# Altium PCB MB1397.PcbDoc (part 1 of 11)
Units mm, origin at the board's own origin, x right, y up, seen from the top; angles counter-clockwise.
Board outline 118.24 x 172.86 mm, 6 copper layers (Top Layer, L2_GND, L3_VCC, L4_SIG, L5_GND, Bottom Layer), stack 1.631 mm thick; 819 components, 632 nets, 2875 pads, 1523 vias.
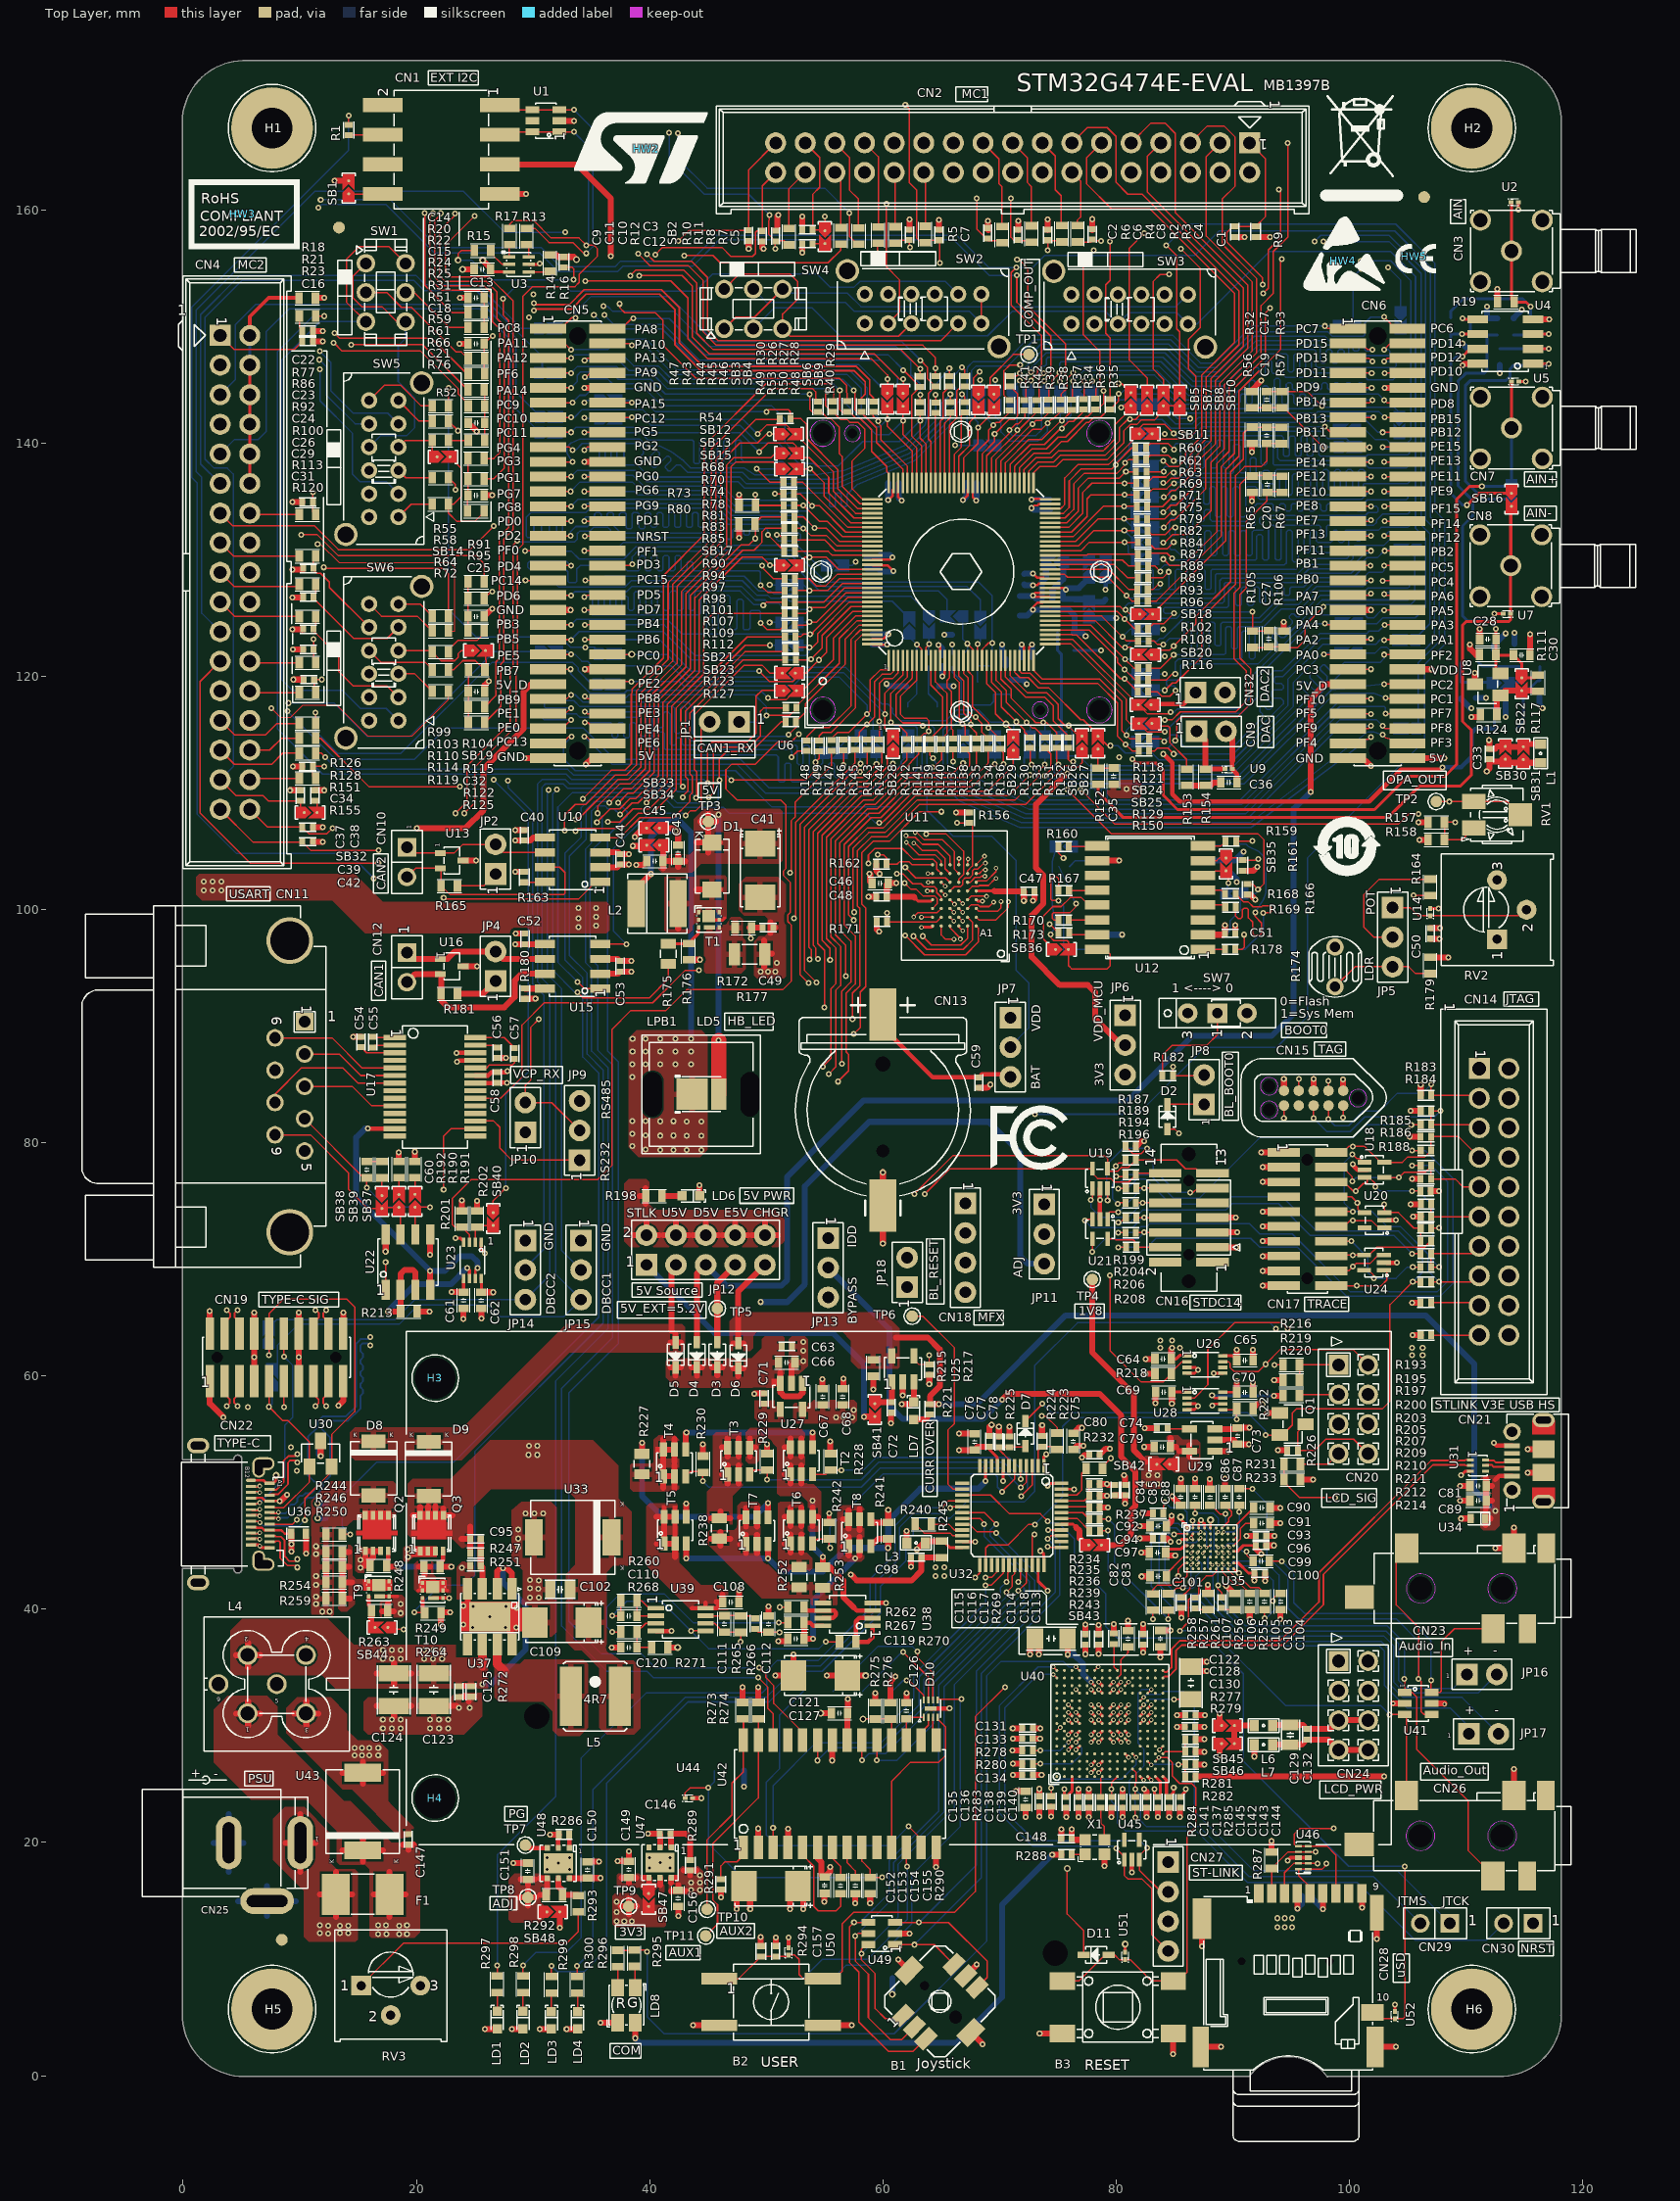
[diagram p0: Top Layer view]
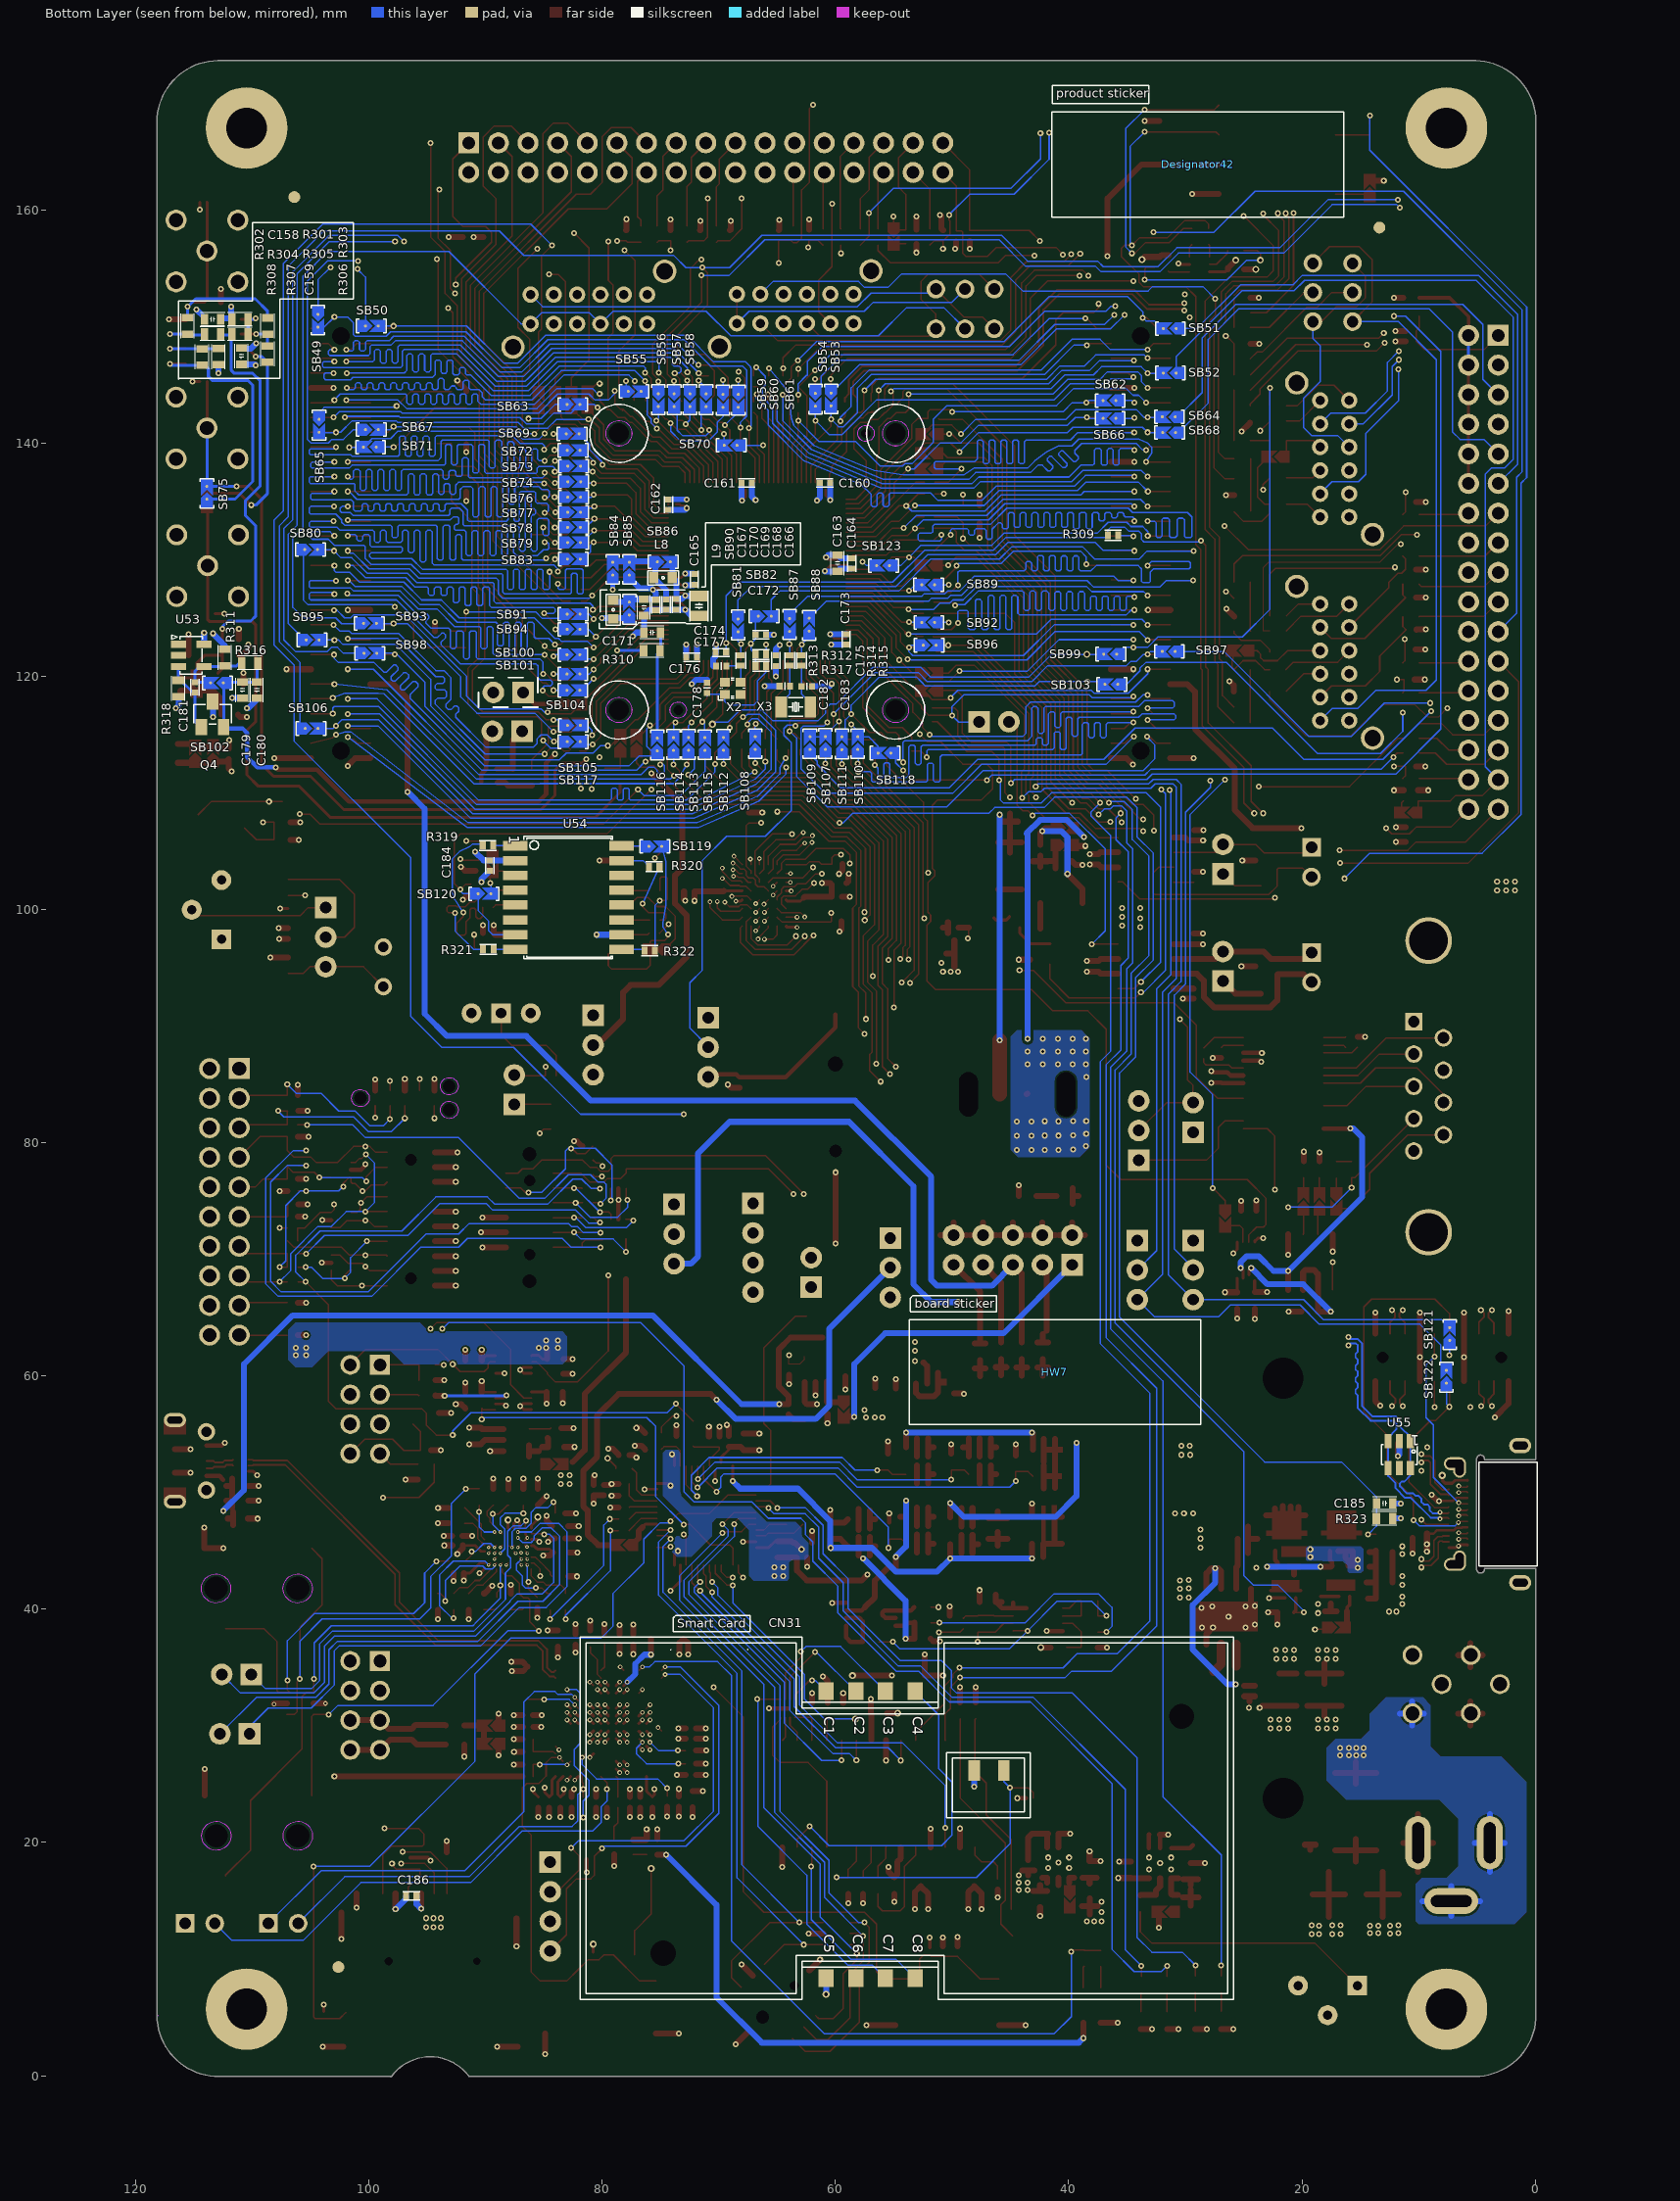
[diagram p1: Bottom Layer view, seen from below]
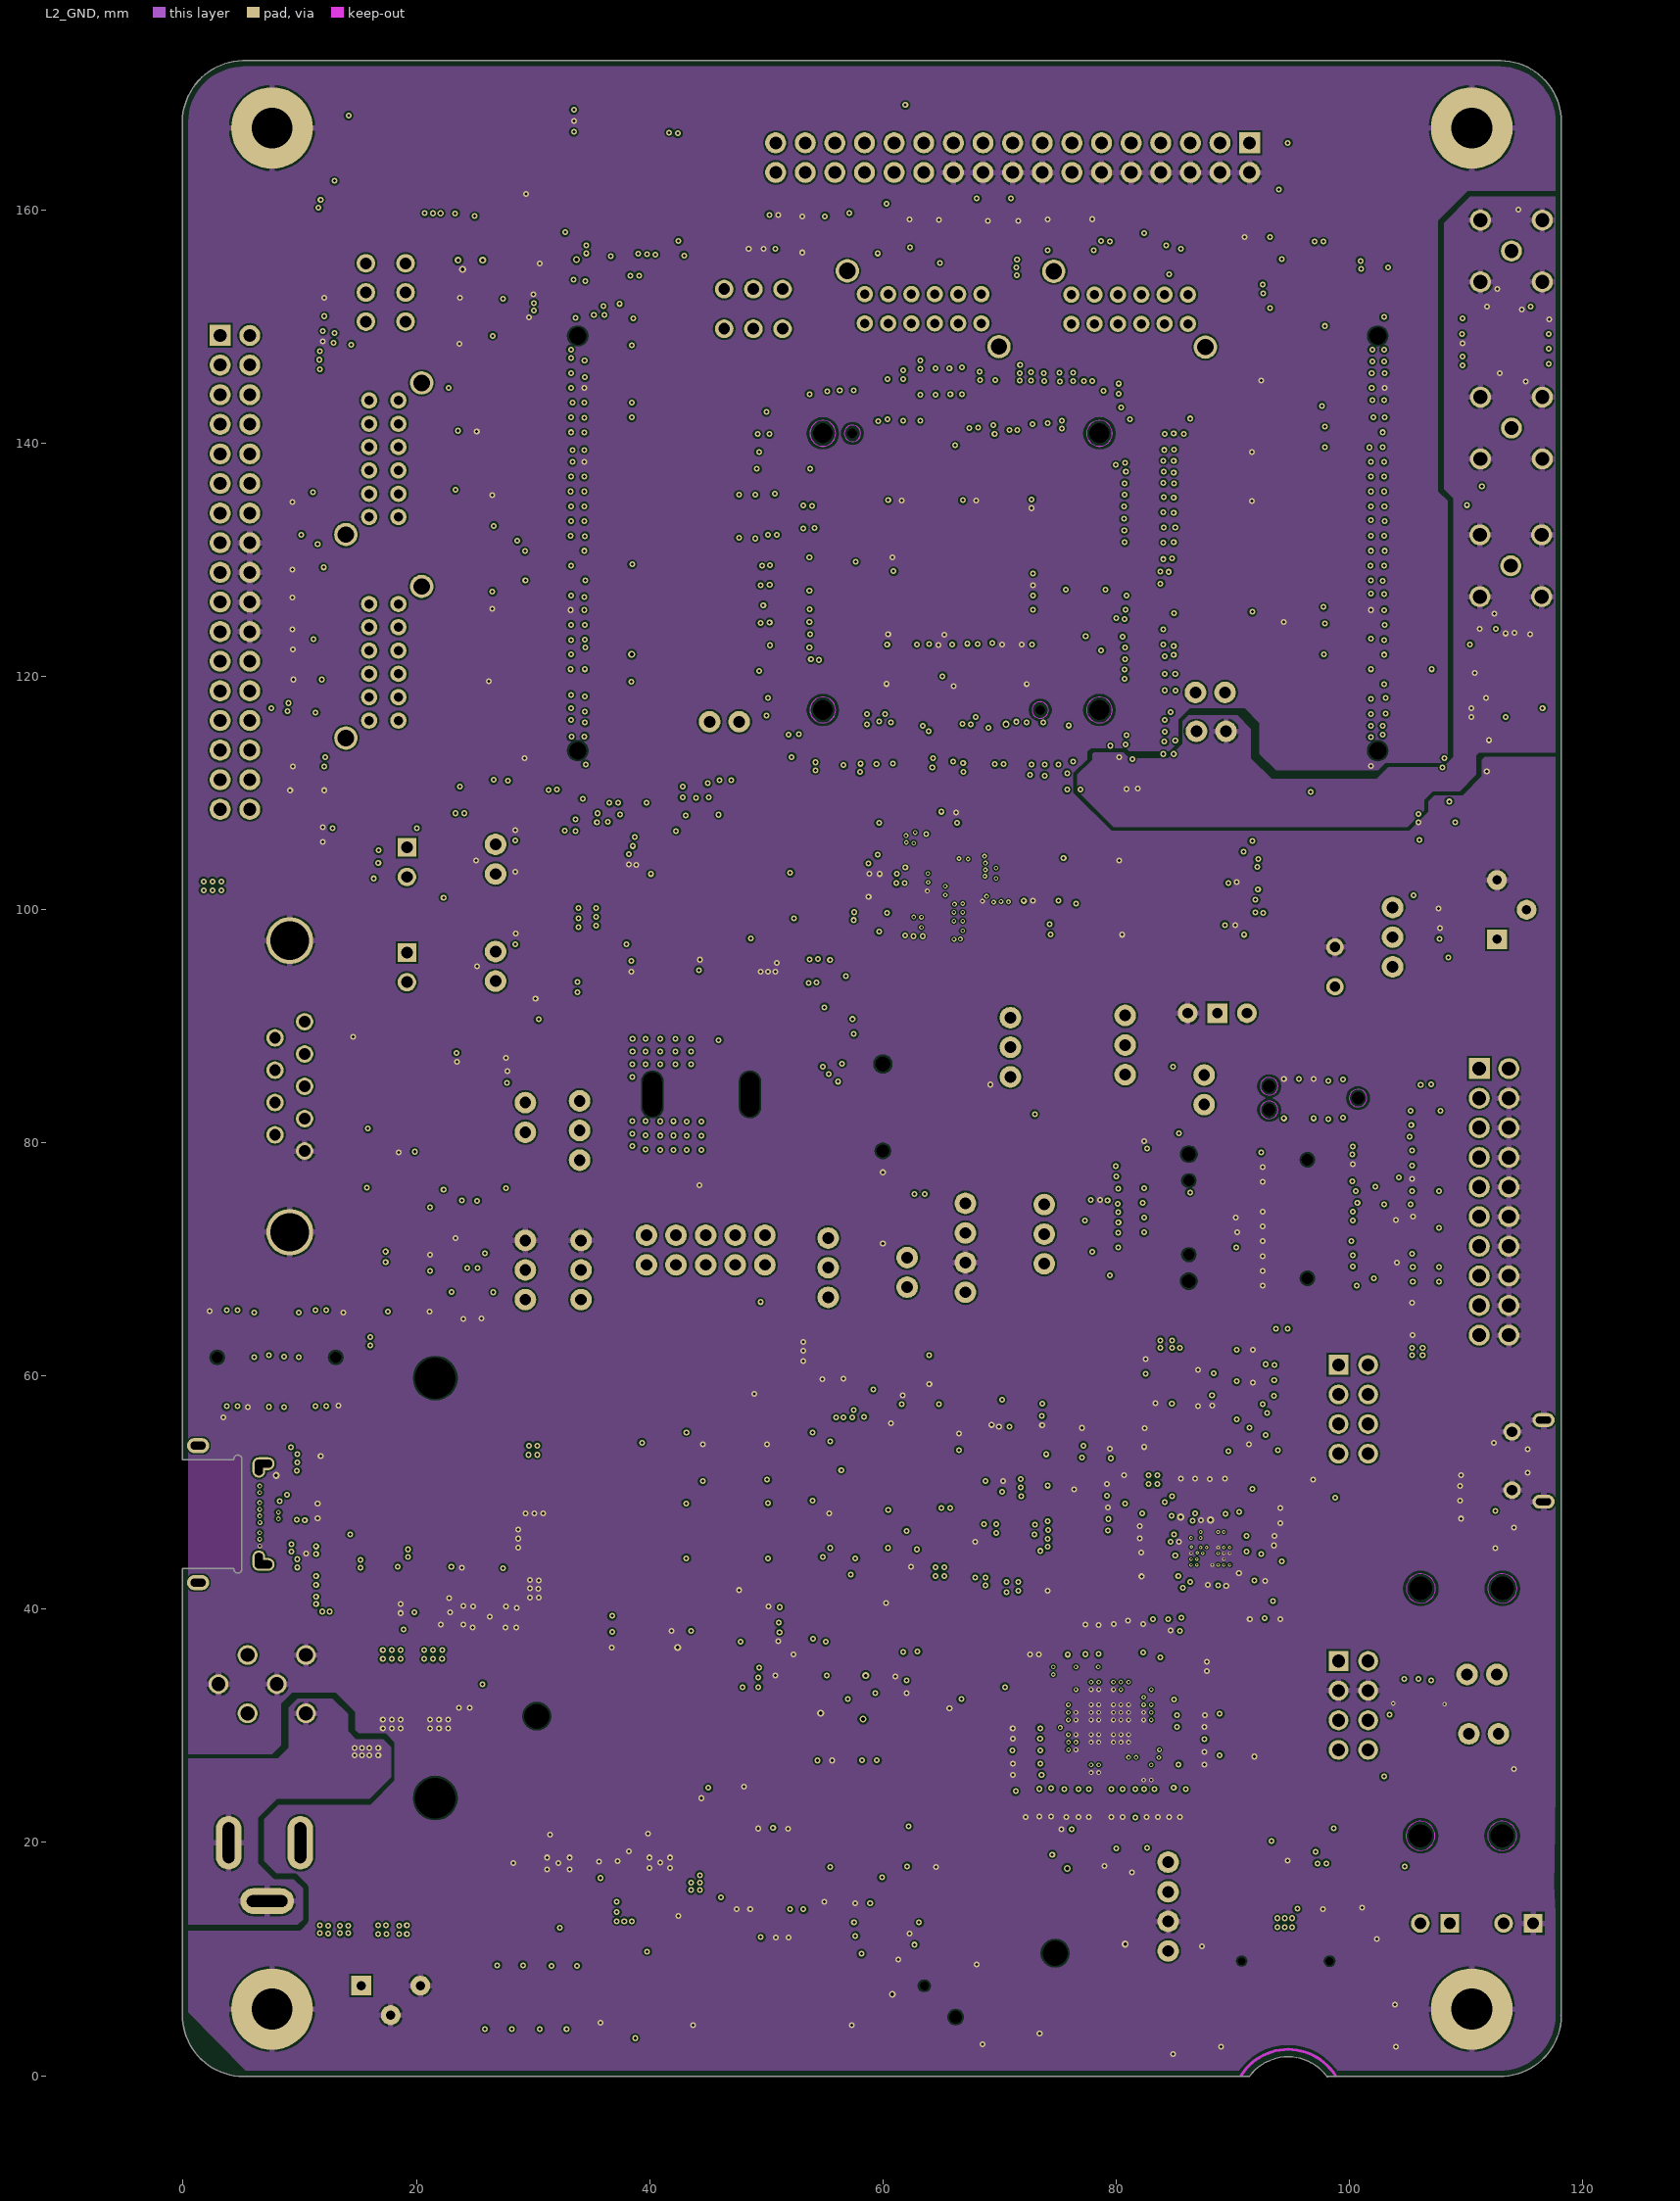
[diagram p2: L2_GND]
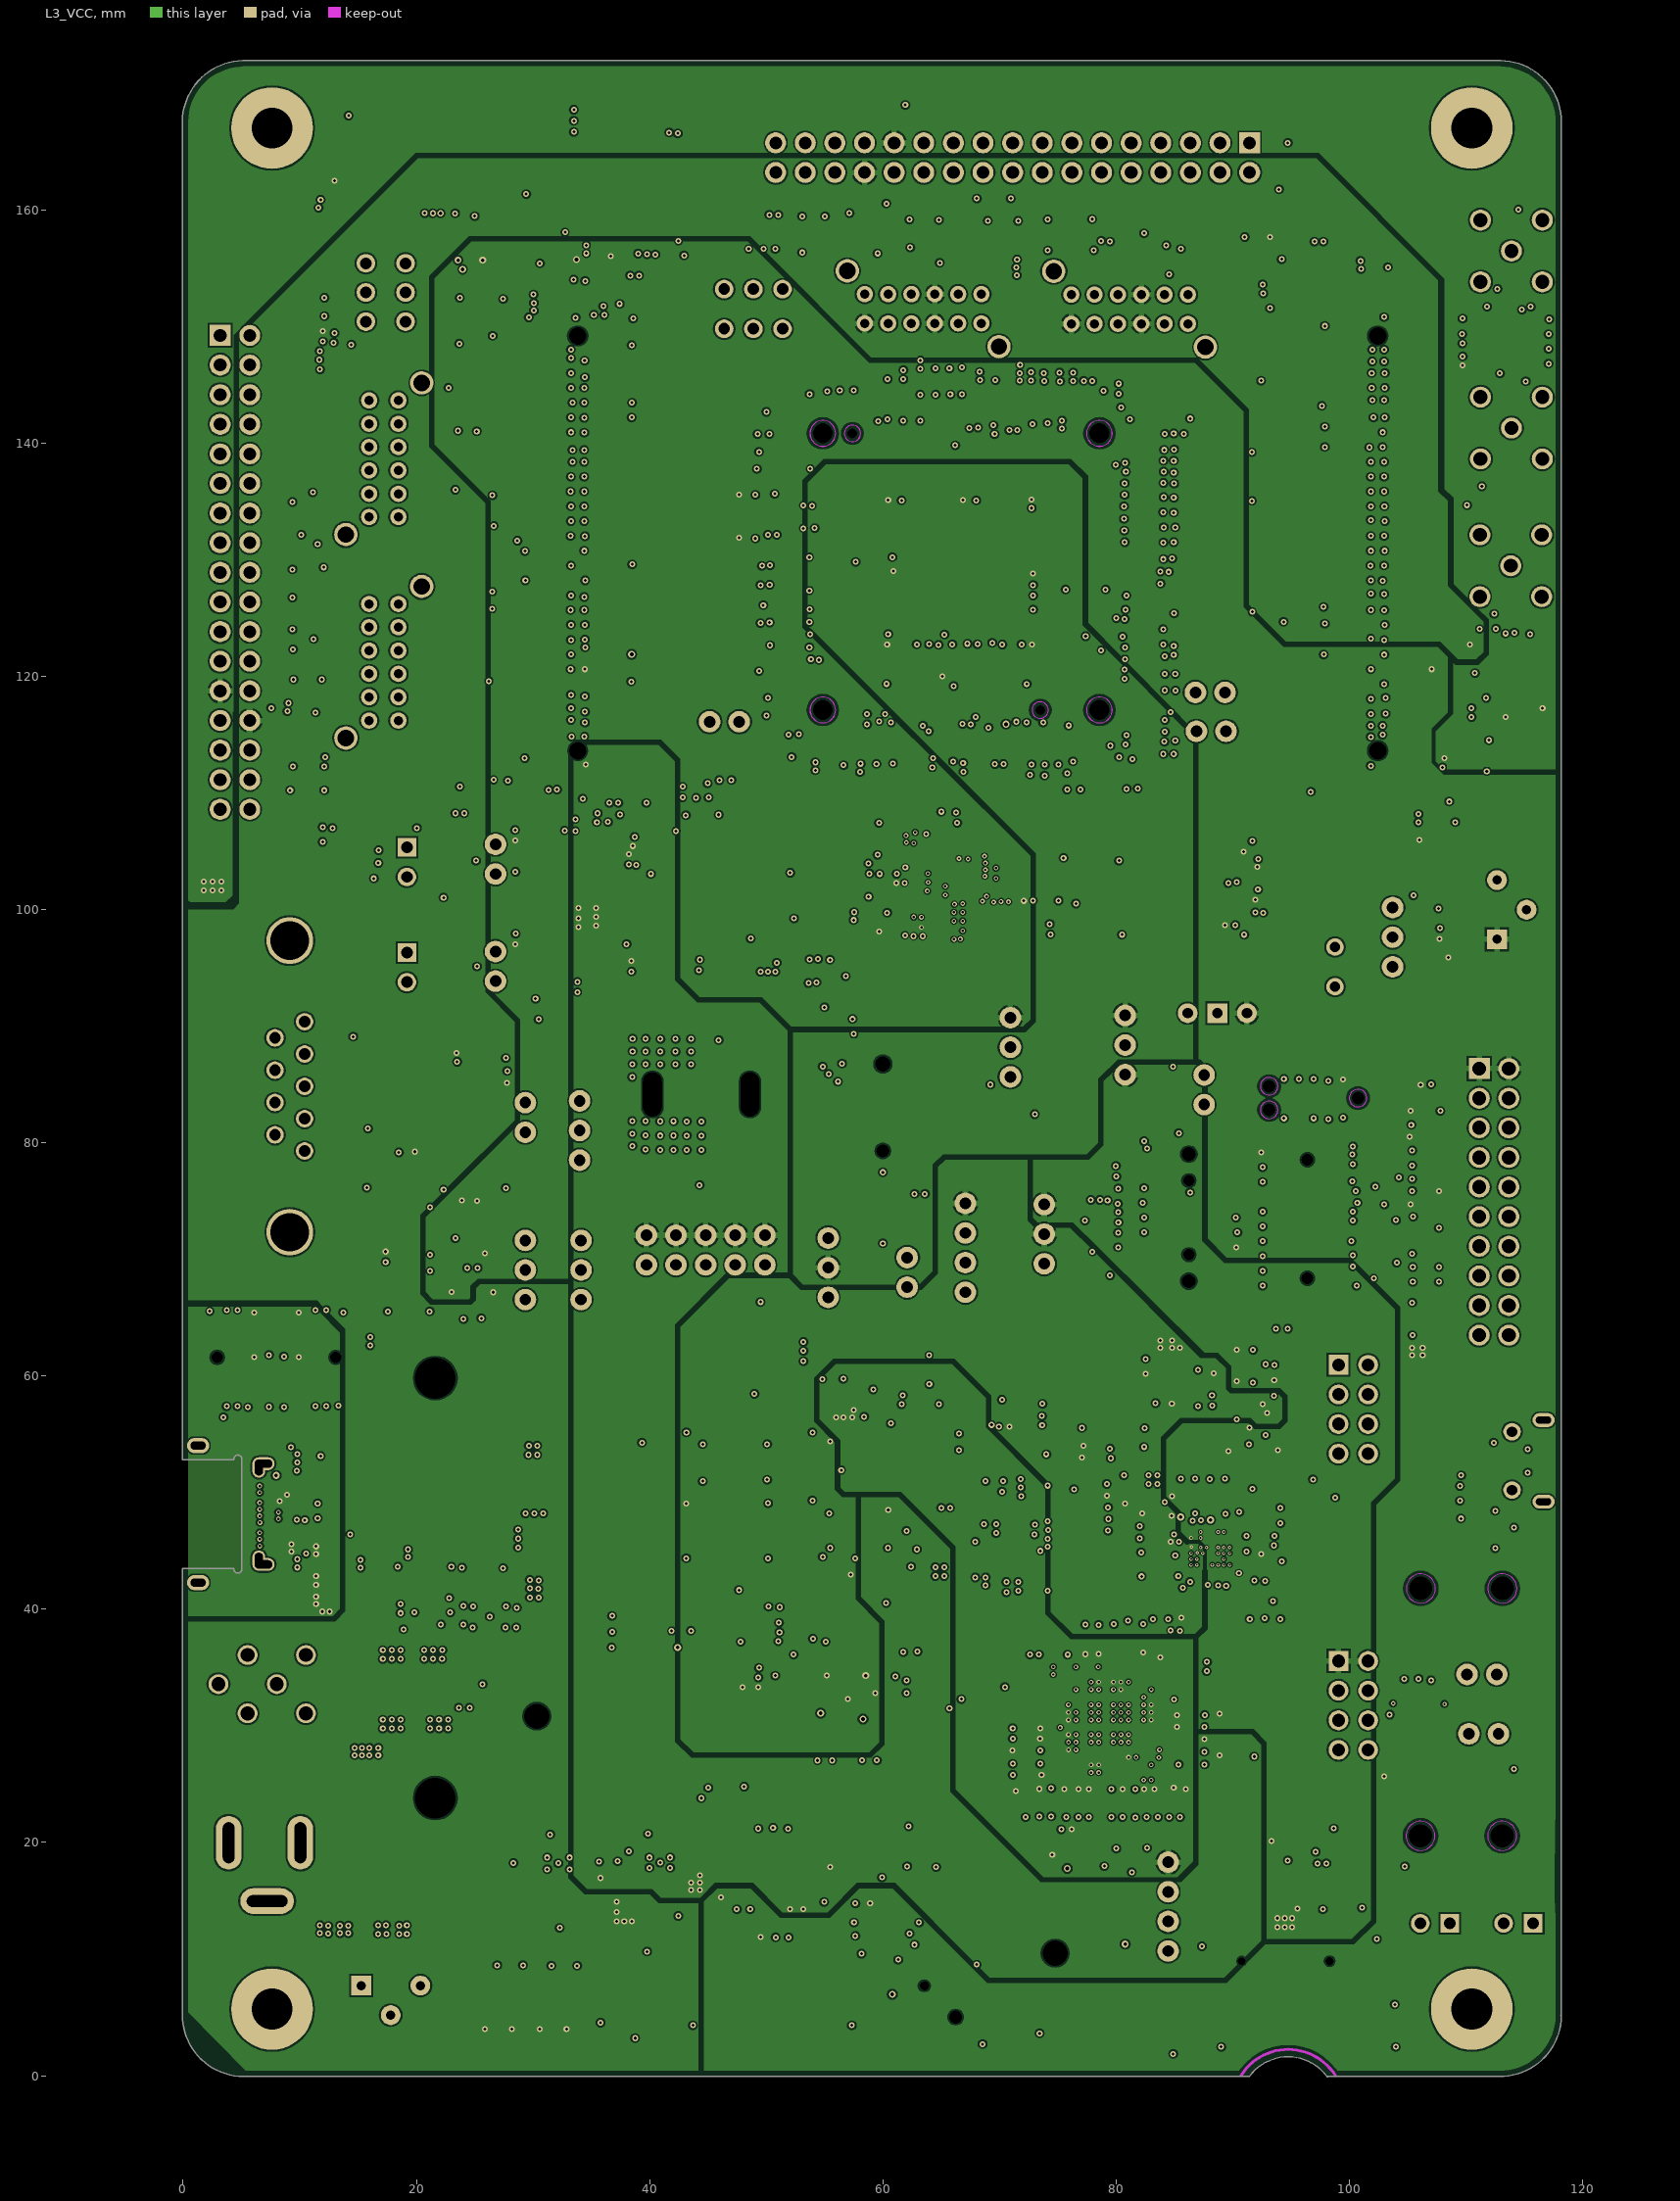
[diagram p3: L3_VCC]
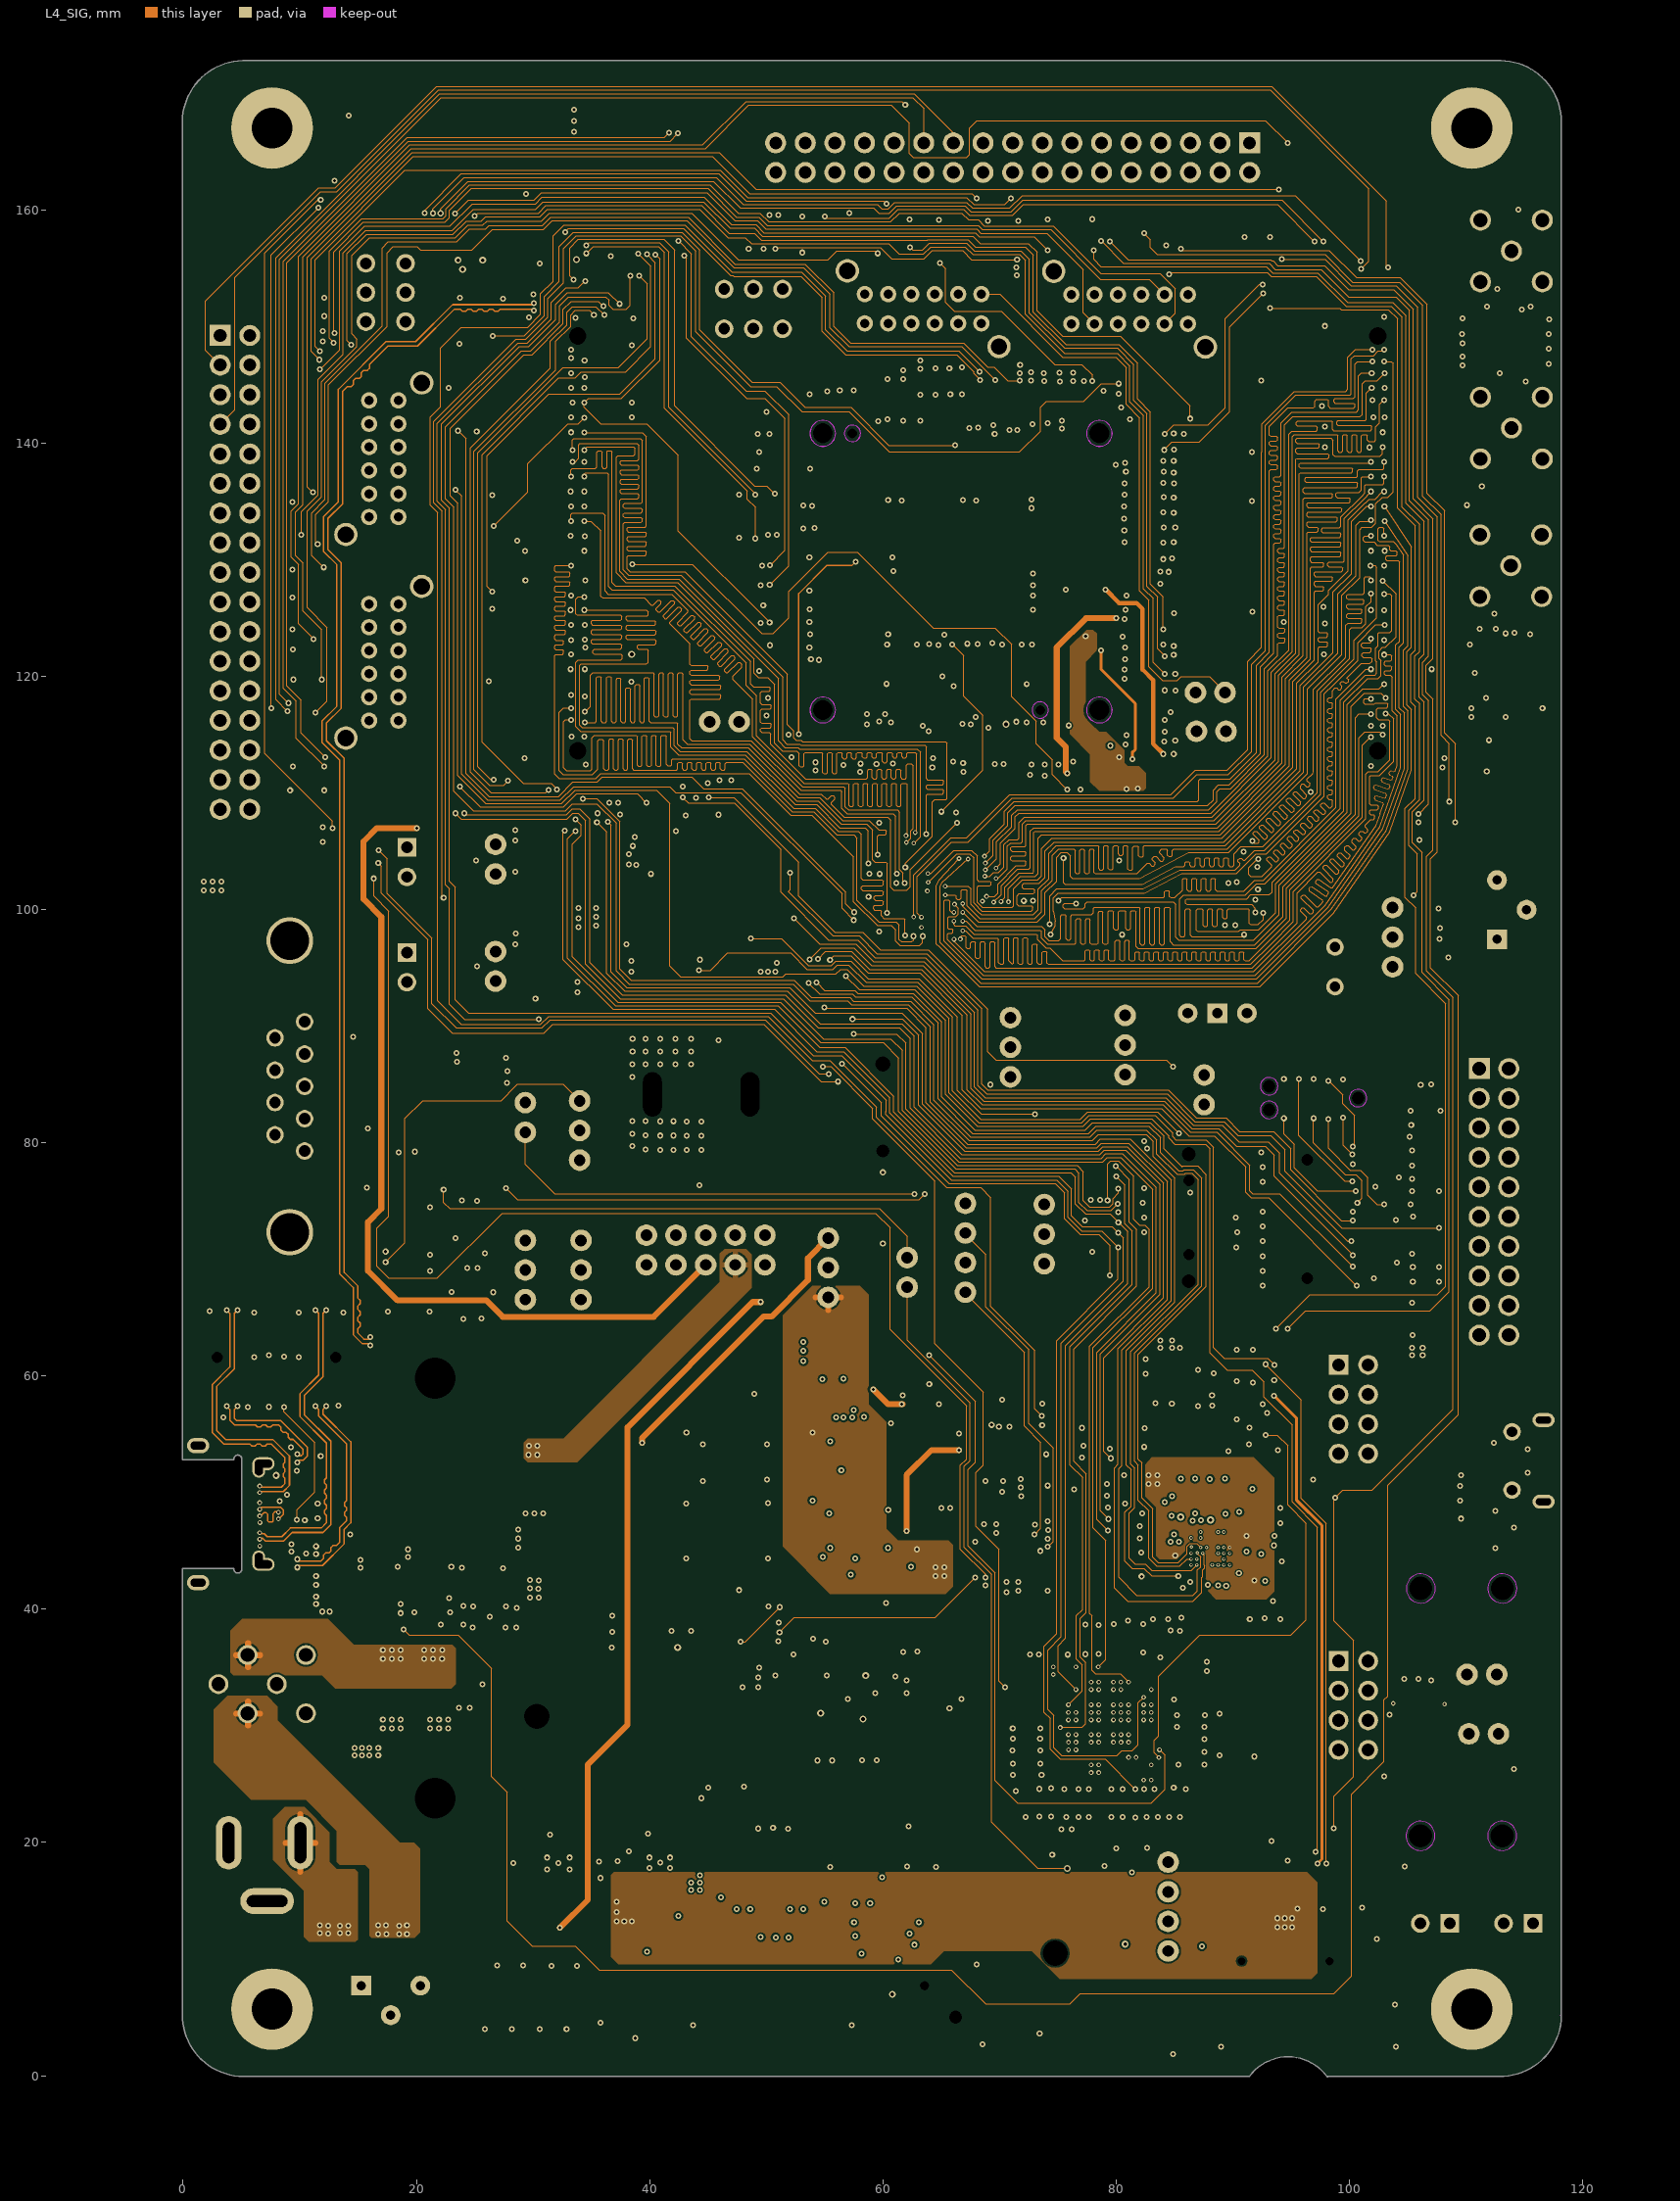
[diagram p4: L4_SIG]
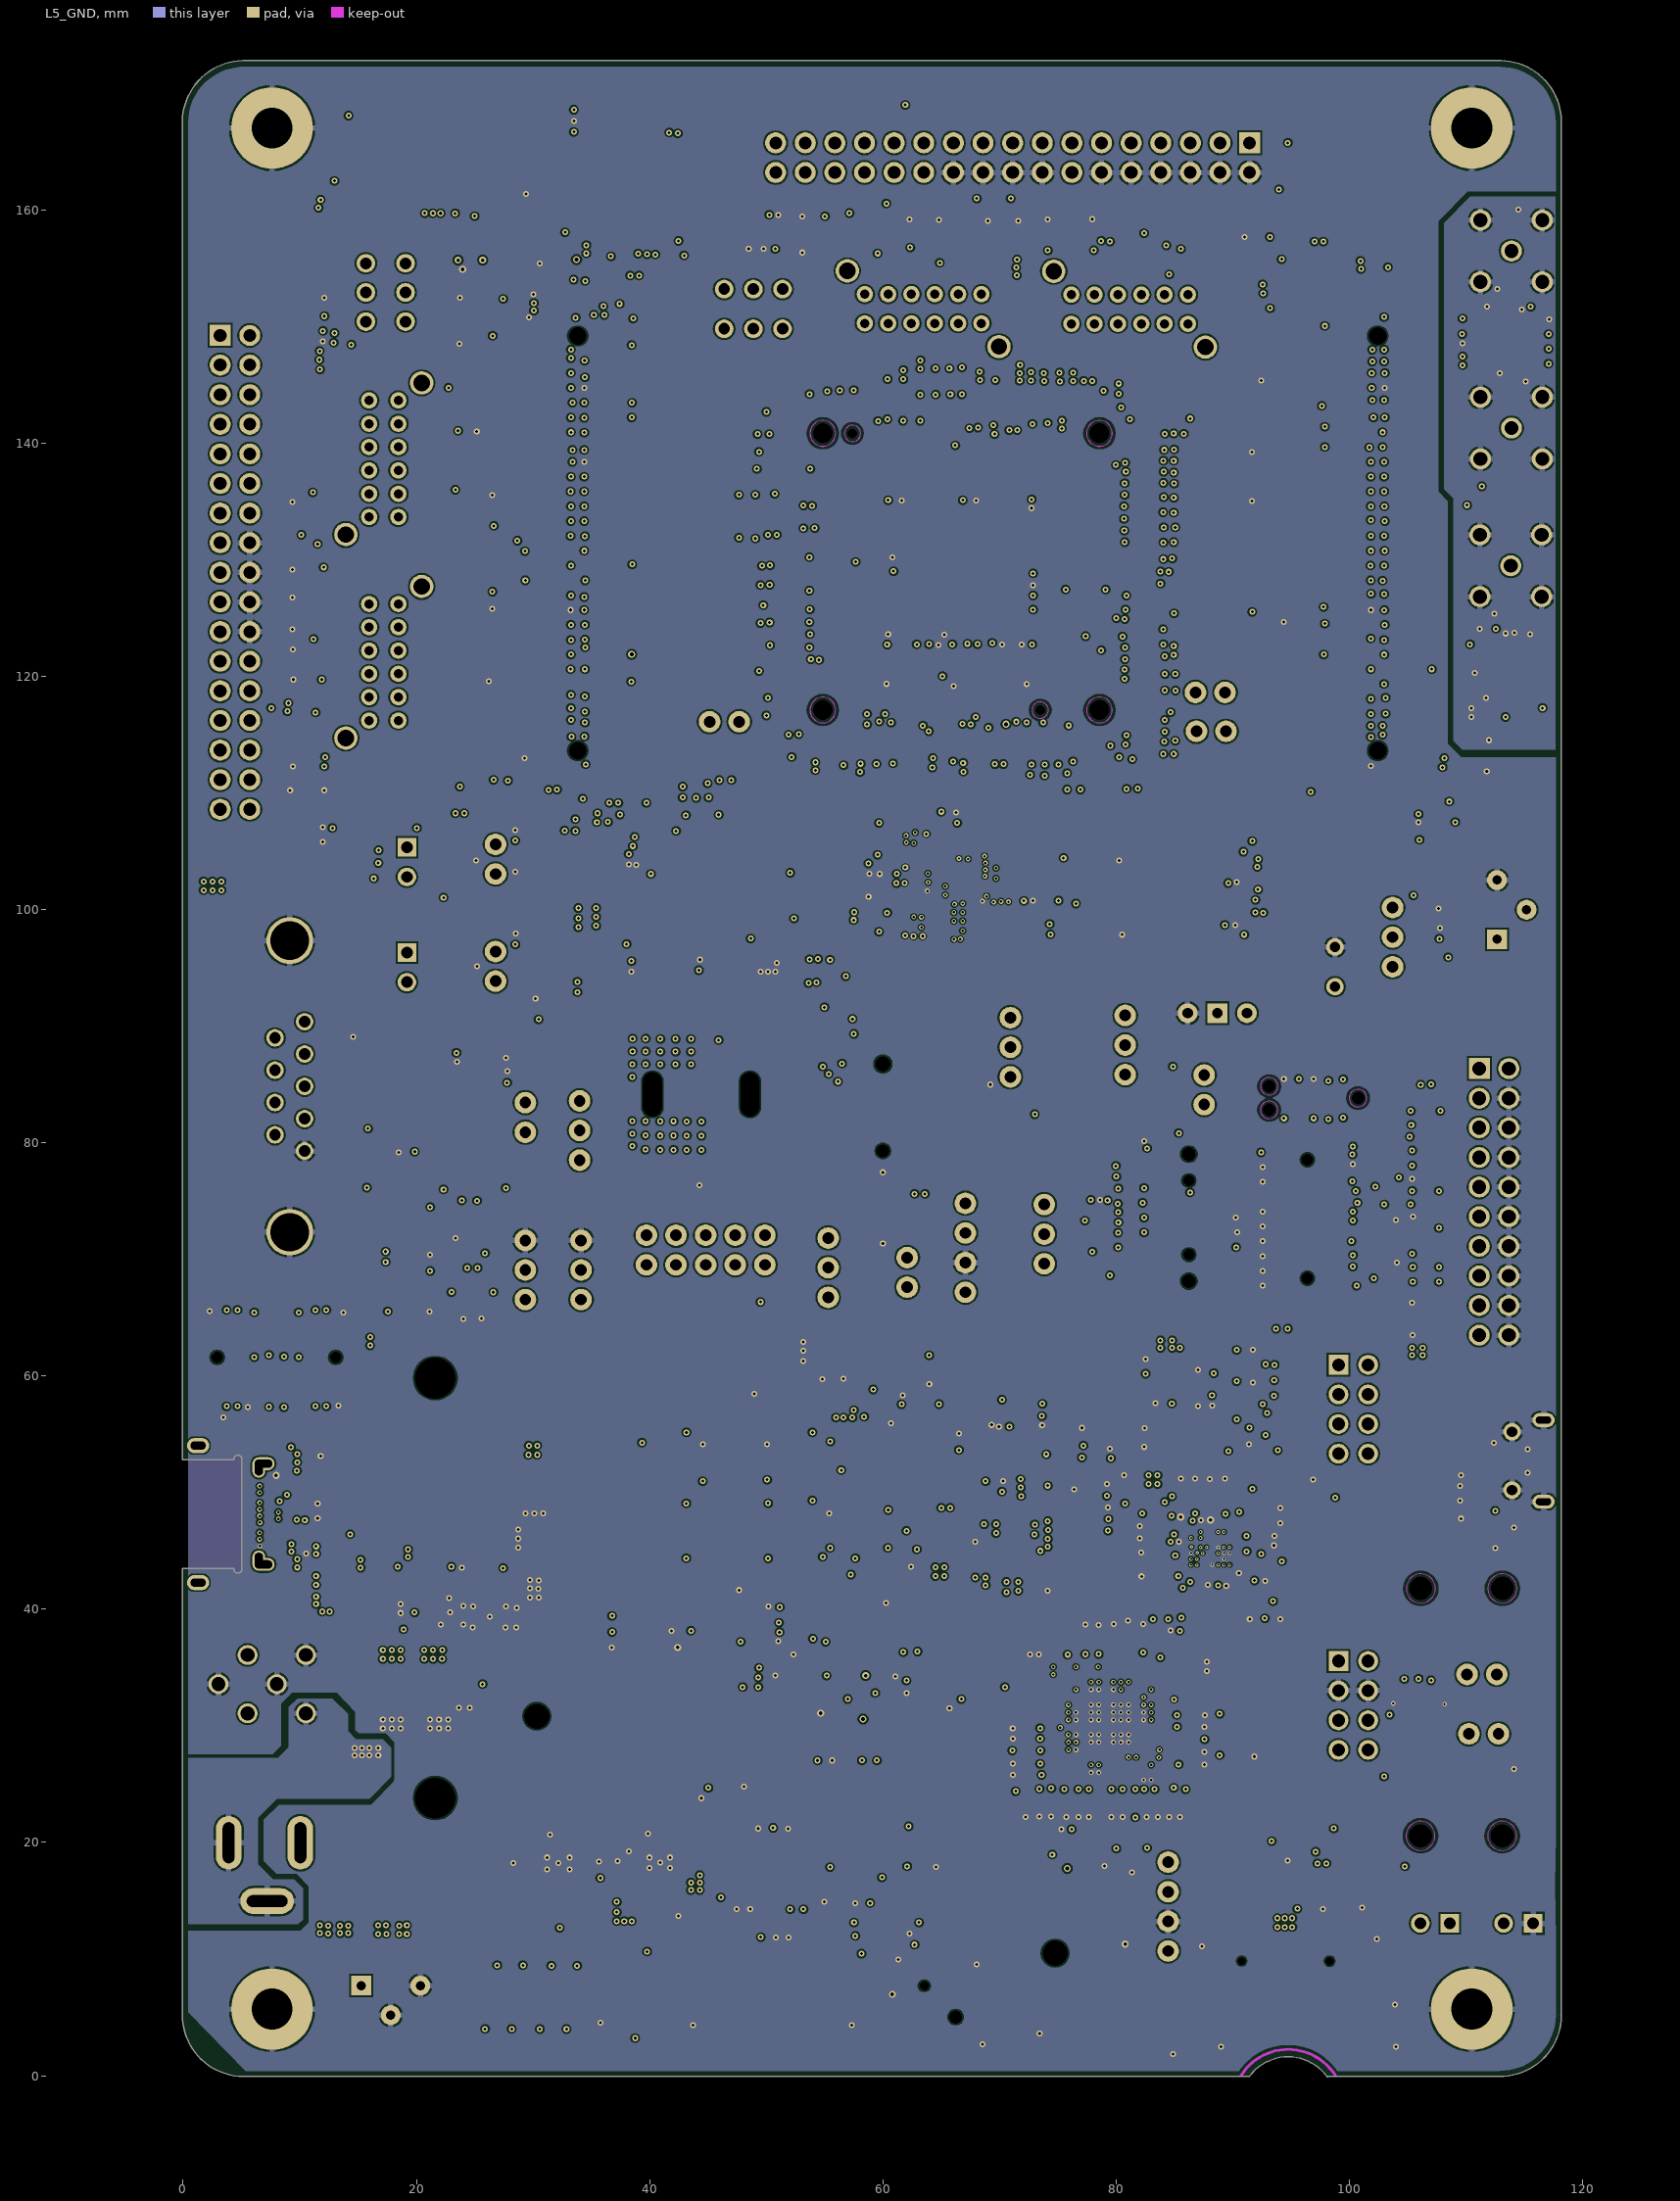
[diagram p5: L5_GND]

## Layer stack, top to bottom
Top Solder: solder mask 0.0102, Solder Resist, Dk 3.5
Top Layer: signal copper 0.0457
Dielectric1: core 0.0991, FR-4, Dk 4.2
L2_GND: signal copper 0.0305
Dielectric2: prepreg 0.127, Dk 4.2
L3_VCC: signal copper 0.0305
Dielectric3: core 0.9652, FR-4, Dk 4.2
L4_SIG: signal copper 0.0305
Dielectric4: prepreg 0.127, Dk 4.2
L5_GND: signal copper 0.0305
Dielectric5: core 0.0991, FR-4, Dk 4.2
Bottom Layer: signal copper 0.0457
Bottom Solder: solder mask 0.0102, Solder Resist, Dk 3.5

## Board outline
-0.064,5.258 -0.064,43.434 cw(c0,43.434) 0,43.498 4.286,43.498 cw(c4.286,43.434) 4.35,43.434 ccw(c4.686,43.434) 5.022,43.434 5.022,52.884 ccw(c5.086,52.884) 5.022,52.883 5.022,52.884 ccw(c4.686,52.884) 4.35,52.884 cw(c4.286,52.884) 4.286,52.82 0,52.82 cw(c0,52.884) -0.064,52.884 -0.064,167.564 cw(c0,167.564) -0.064,167.564 cw(c5.207,167.513) 5.094,172.783 cw(c5.105,172.72) 5.105,172.784 5.156,172.784 cw(c5.207,167.513) 5.258,172.784 112.954,172.784 cw(c112.954,172.72) 112.954,172.784 cw(c112.903,167.513) 118.174,167.513 cw(c112.903,167.513) 118.174,167.462 118.174,24.765 ccw(c118.11,24.765) 118.174,24.766 118.174,24.765 118.174,5.156 ccw(c118.11,5.156) 118.174,5.156 cw(c118.11,5.156) 118.174,5.156 cw(c112.903,5.207) 112.852,-0.064 cw(c112.903,5.207) 112.852,-0.064 98.159,-0.064 cw(c98.116,-0.016) 98.065,-0.054 ccw(c94.742,-2.502) 91.432,-0.038 ccw(c94.742,-2.502) 91.431,-0.038 91.432,-0.038 cw(c91.38,0) 91.38,-0.064 5.156,-0.064 cw(c5.156,0) 5.156,-0.064 cw(c5.207,5.207) -0.064,5.258 cw(c5.207,5.207)
cut-out: -225.071,-180.037 -224.817,-180.037 -224.817,-179.783 -225.071,-179.783

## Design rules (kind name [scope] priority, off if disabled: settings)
Clearance Clearance_C1_RX1 [(ObjectKind = 'Track') And (Net = 'C1_RX1+') vs (ObjectKind = 'Track') And (Net = 'C1_RX1-')] p1: gap=0.226 ignorepadtopadclearanceinfootprint=FALSE except(0: Arc-Hole Track-Hole SMDPad-Hole THPad-Hole Via-Hole Fill-Hole Poly-Hole Region-Hole Text-Hole; 0.152: Arc-Via Track-Via Via-Via)
Clearance Clearance_C1_RX2 [(ObjectKind = 'Track') And (Net ='C1_RX2+') vs (ObjectKind = 'Track') And (Net ='C1_RX2-')] p2: gap=0.226 ignorepadtopadclearanceinfootprint=FALSE except(0: Arc-Hole Track-Hole SMDPad-Hole THPad-Hole Via-Hole Fill-Hole Poly-Hole Region-Hole Text-Hole; 0.203: Via-Via)
Clearance Clearance_C1_TX1 [(ObjectKind = 'Track') And (Net ='C1_TX1-') vs (ObjectKind = 'Track') And (Net ='C1_TX1+')] p3: gap=0.226 ignorepadtopadclearanceinfootprint=FALSE except(0: Arc-Hole Track-Hole SMDPad-Hole THPad-Hole Via-Hole Fill-Hole Poly-Hole Region-Hole Text-Hole; 0.203: Via-Via)
Clearance Clearance_C1_TX2 [(ObjectKind = 'Track') And (Net ='C1_TX2+') vs (ObjectKind = 'Track') And (Net ='C1_TX2-')] p4: gap=0.226 ignorepadtopadclearanceinfootprint=FALSE except(0: Arc-Hole Track-Hole SMDPad-Hole THPad-Hole Via-Hole Fill-Hole Poly-Hole Region-Hole Text-Hole; 0.152: Arc-Via Track-Via Via-Via)
Clearance Clearance_USB_DEV_HS_CN [InNet('USB_DEV_HS_CN_P') vs InNet('USB_DEV_HS_CN_N')] p5: gap=0.226 ignorepadtopadclearanceinfootprint=FALSE except(0: Arc-Hole Track-Hole SMDPad-Hole THPad-Hole Via-Hole Fill-Hole Poly-Hole Region-Hole Text-Hole; 0.203: Via-Via)
Clearance Clearance_USB_D [InNet('USB_DM') vs InNet('USB_DP')] p6: gap=0.226 ignorepadtopadclearanceinfootprint=FALSE except(0: Arc-Hole Track-Hole SMDPad-Hole THPad-Hole Via-Hole Fill-Hole Poly-Hole Region-Hole Text-Hole; 0.152: Arc-Via Track-Via Via-Via)
Clearance Clearance_USB_DEV_HS [InNet('USB_DEV_HS_N') vs InNet('USB_DEV_HS_P')] p7: gap=0.226 ignorepadtopadclearanceinfootprint=FALSE except(0: Arc-Hole Track-Hole SMDPad-Hole THPad-Hole Via-Hole Fill-Hole Poly-Hole Region-Hole Text-Hole; 0.203: Via-Via)
Clearance Clearance_SB [HasFootprint('SOLDER-BRIDGE_R0603-0R')] p8: gap=0.102 ignorepadtopadclearanceinfootprint=FALSE except(0: Arc-Hole Track-Hole SMDPad-Hole THPad-Hole Via-Hole Fill-Hole Poly-Hole Region-Hole Text-Hole)
Clearance Clearance_U11 [WithinRoom('Room_U11','Room_U40')] p9: gap=0.102 ignorepadtopadclearanceinfootprint=FALSE except(0: Arc-Hole Track-Hole SMDPad-Hole THPad-Hole Via-Hole Fill-Hole Poly-Hole Region-Hole Text-Hole)
Clearance Clearance_U35 [All vs WithinRoom('Room_U35')] p10: gap=0.097 ignorepadtopadclearanceinfootprint=FALSE except(0: Arc-Hole Track-Hole SMDPad-Hole THPad-Hole Via-Hole Fill-Hole Poly-Hole Region-Hole Text-Hole)
Clearance Middle-layer-Clearance [(ObjectKind = 'Track') And (Layer = 'L4_SIG') vs (ObjectKind = 'Track') And (Layer = 'L4_SIG')] p11: gap=0.203 ignorepadtopadclearanceinfootprint=FALSE except(0: Arc-Hole Track-Hole SMDPad-Hole THPad-Hole Via-Hole Fill-Hole Poly-Hole Region-Hole Text-Hole; 0.201: Track-Track)
Clearance [All] p12: gap=0.102 ignorepadtopadclearanceinfootprint=FALSE except(0: Arc-Hole Track-Hole SMDPad-Hole THPad-Hole Via-Hole Fill-Hole Poly-Hole Region-Hole Text-Hole; 0.127: Via-Via; 0.152: SMDPad-Fill SMDPad-Poly THPad-Fill THPad-Poly Via-Fill Via-Poly; 0.251: Track-Track; 0.254: Arc-Fill Arc-Poly Track-Fill Track-Poly Fill-Fill Fill-Poly Poly-Poly)
ComponentClearance [All] p1: gap=0.2 collisioncheckmode=3 verticalgap=0.2 showdistances=FALSE
DiffPairsRouting 90ohm [InDifferentialPairClass('90ohm')] p1: maxlimit=0.254 minlimit=0.226 mostfreqgap=0.254 substack1={69586488-EDB0-4C04-BABA-ED091F9F04AA} toplayer_{69586488-edb0-4c04-baba-ed091f9f04aa}_minwidth=0.381 toplayer_{69586488-edb0-4c04-baba-ed091f9f04aa}_maxwidth=0.381 toplayer_{69586488-edb0-4c04-baba-ed091f9f04aa}_prefwidth=0.381 midlayer1_{69586488-edb0-4c04-baba-ed091f9f04aa}_minwidth=0.381 midlayer1_{69586488-edb0-4c04-baba-ed091f9f04aa}_maxwidth=0.381 midlayer1_{69586488-edb0-4c04-baba-ed091f9f04aa}_prefwidth=0.381 midlayer2_{69586488-edb0-4c04-baba-ed091f9f04aa}_minwidth=0.381 midlayer2_{69586488-edb0-4c04-baba-ed091f9f04aa}_maxwidth=0.381 midlayer2_{69586488-edb0-4c04-baba-ed091f9f04aa}_prefwidth=0.381 midlayer3_{69586488-edb0-4c04-baba-ed091f9f04aa}_minwidth=0.381 midlayer3_{69586488-edb0-4c04-baba-ed091f9f04aa}_maxwidth=0.381 midlayer3_{69586488-edb0-4c04-baba-ed091f9f04aa}_prefwidth=0.381 midlayer4_{69586488-edb0-4c04-baba-ed091f9f04aa}_minwidth=0.381 midlayer4_{69586488-edb0-4c04-baba-ed091f9f04aa}_maxwidth=0.381 midlayer4_{69586488-edb0-4c04-baba-ed091f9f04aa}_prefwidth=0.381 bottomlayer_{69586488-edb0-4c04-baba-ed091f9f04aa}_minwidth=0.381 bottomlayer_{69586488-edb0-4c04-baba-ed091f9f04aa}_maxwidth=0.381 bottomlayer_{69586488-edb0-4c04-baba-ed091f9f04aa}_prefwidth=0.381 toplayer_maxgap=0.226 toplayer_prefgap=0.226 toplayer_minwidth=0.155 toplayer_maxwidth=0.381 toplayer_prefwidth=0.381 midlayer1_mingap=0.254 midlayer1_minwidth=0.155 midlayer1_maxwidth=0.381 midlayer1_prefwidth=0.381 midlayer2_mingap=0.254 midlayer2_minwidth=0.155 midlayer2_maxwidth=0.381 midlayer2_prefwidth=0.381 midlayer3_mingap=0.251 midlayer3_maxgap=0.251 midlayer3_prefgap=0.251 midlayer3_minwidth=0.13 midlayer3_maxwidth=0.381 midlayer3_prefwidth=0.381 midlayer4_mingap=0.254 midlayer4_minwidth=0.155 midlayer4_maxwidth=0.381 midlayer4_prefwidth=0.381 bottomlayer_prefgap=0.226 bottomlayer_minwidth=0.155 bottomlayer_maxwidth=0.381 bottomlayer_prefwidth=0.381 substack2={8ACABB3A-8BC0-4983-8633-DD7E9105FD50} toplayer_{8acabb3a-8bc0-4983-8633-dd7e9105fd50}_minwidth=0.381 toplayer_{8acabb3a-8bc0-4983-8633-dd7e9105fd50}_maxwidth=0.381 toplayer_{8acabb3a-8bc0-4983-8633-dd7e9105fd50}_prefwidth=0.381 midlayer1_{8acabb3a-8bc0-4983-8633-dd7e9105fd50}_minwidth=0.381 midlayer1_{8acabb3a-8bc0-4983-8633-dd7e9105fd50}_maxwidth=0.381 midlayer1_{8acabb3a-8bc0-4983-8633-dd7e9105fd50}_prefwidth=0.381 midlayer2_{8acabb3a-8bc0-4983-8633-dd7e9105fd50}_minwidth=0.381 midlayer2_{8acabb3a-8bc0-4983-8633-dd7e9105fd50}_maxwidth=0.381 midlayer2_{8acabb3a-8bc0-4983-8633-dd7e9105fd50}_prefwidth=0.381 midlayer3_{8acabb3a-8bc0-4983-8633-dd7e9105fd50}_minwidth=0.381 midlayer3_{8acabb3a-8bc0-4983-8633-dd7e9105fd50}_maxwidth=0.381 midlayer3_{8acabb3a-8bc0-4983-8633-dd7e9105fd50}_prefwidth=0.381 midlayer4_{8acabb3a-8bc0-4983-8633-dd7e9105fd50}_minwidth=0.381 midlayer4_{8acabb3a-8bc0-4983-8633-dd7e9105fd50}_maxwidth=0.381 midlayer4_{8acabb3a-8bc0-4983-8633-dd7e9105fd50}_prefwidth=0.381 bottomlayer_{8acabb3a-8bc0-4983-8633-dd7e9105fd50}_minwidth=0.381 bottomlayer_{8acabb3a-8bc0-4983-8633-dd7e9105fd50}_maxwidth=0.381 bottomlayer_{8acabb3a-8bc0-4983-8633-dd7e9105fd50}_prefwidth=0.381 substack3={A01F6CDF-020C-4B6A-8E64-FC215A2E0484} toplayer_{a01f6cdf-020c-4b6a-8e64-fc215a2e0484}_minwidth=0.381 toplayer_{a01f6cdf-020c-4b6a-8e64-fc215a2e0484}_maxwidth=0.381 toplayer_{a01f6cdf-020c-4b6a-8e64-fc215a2e0484}_prefwidth=0.381 midlayer1_{a01f6cdf-020c-4b6a-8e64-fc215a2e0484}_minwidth=0.381 midlayer1_{a01f6cdf-020c-4b6a-8e64-fc215a2e0484}_maxwidth=0.381 midlayer1_{a01f6cdf-020c-4b6a-8e64-fc215a2e0484}_prefwidth=0.381 midlayer2_{a01f6cdf-020c-4b6a-8e64-fc215a2e0484}_minwidth=0.381 midlayer2_{a01f6cdf-020c-4b6a-8e64-fc215a2e0484}_maxwidth=0.381 midlayer2_{a01f6cdf-020c-4b6a-8e64-fc215a2e0484}_prefwidth=0.381 midlayer3_{a01f6cdf-020c-4b6a-8e64-fc215a2e0484}_minwidth=0.381 midlayer3_{a01f6cdf-020c-4b6a-8e64-fc215a2e0484}_maxwidth=0.381 midlayer3_{a01f6cdf-020c-4b6a-8e64-fc215a2e0484}_prefwidth=0.381 midlayer4_{a01f6cdf-020c-4b6a-8e64-fc215a2e0484}_minwidth=0.381 midlayer4_{a01f6cdf-020c-4b6a-8e64-fc215a2e0484}_maxwidth=0.381 midlayer4_{a01f6cdf-020c-4b6a-8e64-fc215a2e0484}_prefwidth=0.381 bottomlayer_{a01f6cdf-020c-4b6a-8e64-fc215a2e0484}_minwidth=0.381 bottomlayer_{a01f6cdf-020c-4b6a-8e64-fc215a2e0484}_maxwidth=0.381 bottomlayer_{a01f6cdf-020c-4b6a-8e64-fc215a2e0484}_prefwidth=0.381 substack4={EEF93FF5-C906-4099-87FD-7A69FF981241} toplayer_{eef93ff5-c906-4099-87fd-7a69ff981241}_minwidth=0.381 toplayer_{eef93ff5-c906-4099-87fd-7a69ff981241}_maxwidth=0.381 toplayer_{eef93ff5-c906-4099-87fd-7a69ff981241}_prefwidth=0.381 midlayer1_{eef93ff5-c906-4099-87fd-7a69ff981241}_minwidth=0.381 midlayer1_{eef93ff5-c906-4099-87fd-7a69ff981241}_maxwidth=0.381 midlayer1_{eef93ff5-c906-4099-87fd-7a69ff981241}_prefwidth=0.381 midlayer2_{eef93ff5-c906-4099-87fd-7a69ff981241}_minwidth=0.381 midlayer2_{eef93ff5-c906-4099-87fd-7a69ff981241}_maxwidth=0.381 midlayer2_{eef93ff5-c906-4099-87fd-7a69ff981241}_prefwidth=0.381 midlayer3_{eef93ff5-c906-4099-87fd-7a69ff981241}_minwidth=0.381 midlayer3_{eef93ff5-c906-4099-87fd-7a69ff981241}_maxwidth=0.381 midlayer3_{eef93ff5-c906-4099-87fd-7a69ff981241}_prefwidth=0.381 midlayer4_{eef93ff5-c906-4099-87fd-7a69ff981241}_minwidth=0.381 midlayer4_{eef93ff5-c906-4099-87fd-7a69ff981241}_maxwidth=0.381 midlayer4_{eef93ff5-c906-4099-87fd-7a69ff981241}_prefwidth=0.381 bottomlayer_{eef93ff5-c906-4099-87fd-7a69ff981241}_minwidth=0.381 bottomlayer_{eef93ff5-c906-4099-87fd-7a69ff981241}_maxwidth=0.381 bottomlayer_{eef93ff5-c906-4099-87fd-7a69ff981241}_prefwidth=0.381 substack5={6741F228-4861-413B-9862-25BBBCD38B2A} toplayer_{6741f228-4861-413b-9862-25bbbcd38b2a}_minwidth=0.381 toplayer_{6741f228-4861-413b-9862-25bbbcd38b2a}_maxwidth=0.381 toplayer_{6741f228-4861-413b-9862-25bbbcd38b2a}_prefwidth=0.381 midlayer1_{6741f228-4861-413b-9862-25bbbcd38b2a}_minwidth=0.381 midlayer1_{6741f228-4861-413b-9862-25bbbcd38b2a}_maxwidth=0.381 midlayer1_{6741f228-4861-413b-9862-25bbbcd38b2a}_prefwidth=0.381 midlayer2_{6741f228-4861-413b-9862-25bbbcd38b2a}_minwidth=0.381 midlayer2_{6741f228-4861-413b-9862-25bbbcd38b2a}_maxwidth=0.381 midlayer2_{6741f228-4861-413b-9862-25bbbcd38b2a}_prefwidth=0.381 midlayer3_{6741f228-4861-413b-9862-25bbbcd38b2a}_minwidth=0.381 midlayer3_{6741f228-4861-413b-9862-25bbbcd38b2a}_maxwidth=0.381 midlayer3_{6741f228-4861-413b-9862-25bbbcd38b2a}_prefwidth=0.381 midlayer4_{6741f228-4861-413b-9862-25bbbcd38b2a}_minwidth=0.381 midlayer4_{6741f228-4861-413b-9862-25bbbcd38b2a}_maxwidth=0.381 midlayer4_{6741f228-4861-413b-9862-25bbbcd38b2a}_prefwidth=0.381 bottomlayer_{6741f228-4861-413b-9862-25bbbcd38b2a}_minwidth=0.381 bottomlayer_{6741f228-4861-413b-9862-25bbbcd38b2a}_maxwidth=0.381 bottomlayer_{6741f228-4861-413b-9862-25bbbcd38b2a}_prefwidth=0.381 maxuncoupledlength=12.7
DiffPairsRouting 100ohm [InDifferentialPairClass('100OHM')] p2: maxlimit=0.277 minlimit=0.104 mostfreqgap=0.277 substack1={69586488-EDB0-4C04-BABA-ED091F9F04AA} toplayer_{69586488-edb0-4c04-baba-ed091f9f04aa}_minwidth=0.381 toplayer_{69586488-edb0-4c04-baba-ed091f9f04aa}_maxwidth=0.381 toplayer_{69586488-edb0-4c04-baba-ed091f9f04aa}_prefwidth=0.381 midlayer1_{69586488-edb0-4c04-baba-ed091f9f04aa}_minwidth=0.381 midlayer1_{69586488-edb0-4c04-baba-ed091f9f04aa}_maxwidth=0.381 midlayer1_{69586488-edb0-4c04-baba-ed091f9f04aa}_prefwidth=0.381 midlayer2_{69586488-edb0-4c04-baba-ed091f9f04aa}_minwidth=0.381 midlayer2_{69586488-edb0-4c04-baba-ed091f9f04aa}_maxwidth=0.381 midlayer2_{69586488-edb0-4c04-baba-ed091f9f04aa}_prefwidth=0.381 midlayer3_{69586488-edb0-4c04-baba-ed091f9f04aa}_minwidth=0.381 midlayer3_{69586488-edb0-4c04-baba-ed091f9f04aa}_maxwidth=0.381 midlayer3_{69586488-edb0-4c04-baba-ed091f9f04aa}_prefwidth=0.381 midlayer4_{69586488-edb0-4c04-baba-ed091f9f04aa}_minwidth=0.381 midlayer4_{69586488-edb0-4c04-baba-ed091f9f04aa}_maxwidth=0.381 midlayer4_{69586488-edb0-4c04-baba-ed091f9f04aa}_prefwidth=0.381 bottomlayer_{69586488-edb0-4c04-baba-ed091f9f04aa}_minwidth=0.381 bottomlayer_{69586488-edb0-4c04-baba-ed091f9f04aa}_maxwidth=0.381 bottomlayer_{69586488-edb0-4c04-baba-ed091f9f04aa}_prefwidth=0.381 toplayer_mingap=0.251 toplayer_maxgap=0.251 toplayer_prefgap=0.251 toplayer_minwidth=0.155 toplayer_maxwidth=0.381 toplayer_prefwidth=0.381 midlayer1_mingap=0.254 midlayer1_maxgap=0.254 midlayer1_prefgap=0.254 midlayer1_minwidth=0.155 midlayer1_maxwidth=0.381 midlayer1_prefwidth=0.381 midlayer2_minwidth=0.155 midlayer2_maxwidth=0.381 midlayer2_prefwidth=0.381 midlayer3_minwidth=0.155 midlayer3_maxwidth=0.381 midlayer3_prefwidth=0.381 midlayer4_mingap=0.254 midlayer4_maxgap=0.254 midlayer4_prefgap=0.254 midlayer4_minwidth=0.155 midlayer4_maxwidth=0.381 midlayer4_prefwidth=0.381 bottomlayer_mingap=0.13 bottomlayer_maxgap=0.251 bottomlayer_prefgap=0.251 bottomlayer_minwidth=0.155 bottomlayer_maxwidth=0.381 bottomlayer_prefwidth=0.381 substack2={8ACABB3A-8BC0-4983-8633-DD7E9105FD50} toplayer_{8acabb3a-8bc0-4983-8633-dd7e9105fd50}_minwidth=0.381 toplayer_{8acabb3a-8bc0-4983-8633-dd7e9105fd50}_maxwidth=0.381 toplayer_{8acabb3a-8bc0-4983-8633-dd7e9105fd50}_prefwidth=0.381 midlayer1_{8acabb3a-8bc0-4983-8633-dd7e9105fd50}_minwidth=0.381 midlayer1_{8acabb3a-8bc0-4983-8633-dd7e9105fd50}_maxwidth=0.381 midlayer1_{8acabb3a-8bc0-4983-8633-dd7e9105fd50}_prefwidth=0.381 midlayer2_{8acabb3a-8bc0-4983-8633-dd7e9105fd50}_minwidth=0.381 midlayer2_{8acabb3a-8bc0-4983-8633-dd7e9105fd50}_maxwidth=0.381 midlayer2_{8acabb3a-8bc0-4983-8633-dd7e9105fd50}_prefwidth=0.381 midlayer3_{8acabb3a-8bc0-4983-8633-dd7e9105fd50}_minwidth=0.381 midlayer3_{8acabb3a-8bc0-4983-8633-dd7e9105fd50}_maxwidth=0.381 midlayer3_{8acabb3a-8bc0-4983-8633-dd7e9105fd50}_prefwidth=0.381 midlayer4_{8acabb3a-8bc0-4983-8633-dd7e9105fd50}_minwidth=0.381 midlayer4_{8acabb3a-8bc0-4983-8633-dd7e9105fd50}_maxwidth=0.381 midlayer4_{8acabb3a-8bc0-4983-8633-dd7e9105fd50}_prefwidth=0.381 bottomlayer_{8acabb3a-8bc0-4983-8633-dd7e9105fd50}_minwidth=0.381 bottomlayer_{8acabb3a-8bc0-4983-8633-dd7e9105fd50}_maxwidth=0.381 bottomlayer_{8acabb3a-8bc0-4983-8633-dd7e9105fd50}_prefwidth=0.381 substack3={A01F6CDF-020C-4B6A-8E64-FC215A2E0484} toplayer_{a01f6cdf-020c-4b6a-8e64-fc215a2e0484}_minwidth=0.381 toplayer_{a01f6cdf-020c-4b6a-8e64-fc215a2e0484}_maxwidth=0.381 toplayer_{a01f6cdf-020c-4b6a-8e64-fc215a2e0484}_prefwidth=0.381 midlayer1_{a01f6cdf-020c-4b6a-8e64-fc215a2e0484}_minwidth=0.381 midlayer1_{a01f6cdf-020c-4b6a-8e64-fc215a2e0484}_maxwidth=0.381 midlayer1_{a01f6cdf-020c-4b6a-8e64-fc215a2e0484}_prefwidth=0.381 midlayer2_{a01f6cdf-020c-4b6a-8e64-fc215a2e0484}_minwidth=0.381 midlayer2_{a01f6cdf-020c-4b6a-8e64-fc215a2e0484}_maxwidth=0.381 midlayer2_{a01f6cdf-020c-4b6a-8e64-fc215a2e0484}_prefwidth=0.381 midlayer3_{a01f6cdf-020c-4b6a-8e64-fc215a2e0484}_minwidth=0.381 midlayer3_{a01f6cdf-020c-4b6a-8e64-fc215a2e0484}_maxwidth=0.381 midlayer3_{a01f6cdf-020c-4b6a-8e64-fc215a2e0484}_prefwidth=0.381 midlayer4_{a01f6cdf-020c-4b6a-8e64-fc215a2e0484}_minwidth=0.381 midlayer4_{a01f6cdf-020c-4b6a-8e64-fc215a2e0484}_maxwidth=0.381 midlayer4_{a01f6cdf-020c-4b6a-8e64-fc215a2e0484}_prefwidth=0.381 bottomlayer_{a01f6cdf-020c-4b6a-8e64-fc215a2e0484}_minwidth=0.381 bottomlayer_{a01f6cdf-020c-4b6a-8e64-fc215a2e0484}_maxwidth=0.381 bottomlayer_{a01f6cdf-020c-4b6a-8e64-fc215a2e0484}_prefwidth=0.381 substack4={EEF93FF5-C906-4099-87FD-7A69FF981241} toplayer_{eef93ff5-c906-4099-87fd-7a69ff981241}_minwidth=0.381 toplayer_{eef93ff5-c906-4099-87fd-7a69ff981241}_maxwidth=0.381 toplayer_{eef93ff5-c906-4099-87fd-7a69ff981241}_prefwidth=0.381 midlayer1_{eef93ff5-c906-4099-87fd-7a69ff981241}_minwidth=0.381 midlayer1_{eef93ff5-c906-4099-87fd-7a69ff981241}_maxwidth=0.381 midlayer1_{eef93ff5-c906-4099-87fd-7a69ff981241}_prefwidth=0.381 midlayer2_{eef93ff5-c906-4099-87fd-7a69ff981241}_minwidth=0.381 midlayer2_{eef93ff5-c906-4099-87fd-7a69ff981241}_maxwidth=0.381 midlayer2_{eef93ff5-c906-4099-87fd-7a69ff981241}_prefwidth=0.381 midlayer3_{eef93ff5-c906-4099-87fd-7a69ff981241}_minwidth=0.381 midlayer3_{eef93ff5-c906-4099-87fd-7a69ff981241}_maxwidth=0.381 midlayer3_{eef93ff5-c906-4099-87fd-7a69ff981241}_prefwidth=0.381 midlayer4_{eef93ff5-c906-4099-87fd-7a69ff981241}_minwidth=0.381 midlayer4_{eef93ff5-c906-4099-87fd-7a69ff981241}_maxwidth=0.381 midlayer4_{eef93ff5-c906-4099-87fd-7a69ff981241}_prefwidth=0.381 bottomlayer_{eef93ff5-c906-4099-87fd-7a69ff981241}_minwidth=0.381 bottomlayer_{eef93ff5-c906-4099-87fd-7a69ff981241}_maxwidth=0.381 bottomlayer_{eef93ff5-c906-4099-87fd-7a69ff981241}_prefwidth=0.381 substack5={6741F228-4861-413B-9862-25BBBCD38B2A} toplayer_{6741f228-4861-413b-9862-25bbbcd38b2a}_minwidth=0.381 toplayer_{6741f228-4861-413b-9862-25bbbcd38b2a}_maxwidth=0.381 toplayer_{6741f228-4861-413b-9862-25bbbcd38b2a}_prefwidth=0.381 midlayer1_{6741f228-4861-413b-9862-25bbbcd38b2a}_minwidth=0.381 midlayer1_{6741f228-4861-413b-9862-25bbbcd38b2a}_maxwidth=0.381 midlayer1_{6741f228-4861-413b-9862-25bbbcd38b2a}_prefwidth=0.381 midlayer2_{6741f228-4861-413b-9862-25bbbcd38b2a}_minwidth=0.381 midlayer2_{6741f228-4861-413b-9862-25bbbcd38b2a}_maxwidth=0.381 midlayer2_{6741f228-4861-413b-9862-25bbbcd38b2a}_prefwidth=0.381 midlayer3_{6741f228-4861-413b-9862-25bbbcd38b2a}_minwidth=0.381 midlayer3_{6741f228-4861-413b-9862-25bbbcd38b2a}_maxwidth=0.381 midlayer3_{6741f228-4861-413b-9862-25bbbcd38b2a}_prefwidth=0.381 midlayer4_{6741f228-4861-413b-9862-25bbbcd38b2a}_minwidth=0.381 midlayer4_{6741f228-4861-413b-9862-25bbbcd38b2a}_maxwidth=0.381 midlayer4_{6741f228-4861-413b-9862-25bbbcd38b2a}_prefwidth=0.381 bottomlayer_{6741f228-4861-413b-9862-25bbbcd38b2a}_minwidth=0.381 bottomlayer_{6741f228-4861-413b-9862-25bbbcd38b2a}_maxwidth=0.381 bottomlayer_{6741f228-4861-413b-9862-25bbbcd38b2a}_prefwidth=0.381 maxuncoupledlength=12.7
DiffPairsRouting [All] p3: maxlimit=0.254 minlimit=0.254 mostfreqgap=0.254 substack1={69586488-EDB0-4C04-BABA-ED091F9F04AA} toplayer_{69586488-edb0-4c04-baba-ed091f9f04aa}_minwidth=0.381 toplayer_{69586488-edb0-4c04-baba-ed091f9f04aa}_maxwidth=0.381 toplayer_{69586488-edb0-4c04-baba-ed091f9f04aa}_prefwidth=0.381 midlayer1_{69586488-edb0-4c04-baba-ed091f9f04aa}_minwidth=0.381 midlayer1_{69586488-edb0-4c04-baba-ed091f9f04aa}_maxwidth=0.381 midlayer1_{69586488-edb0-4c04-baba-ed091f9f04aa}_prefwidth=0.381 midlayer2_{69586488-edb0-4c04-baba-ed091f9f04aa}_minwidth=0.381 midlayer2_{69586488-edb0-4c04-baba-ed091f9f04aa}_maxwidth=0.381 midlayer2_{69586488-edb0-4c04-baba-ed091f9f04aa}_prefwidth=0.381 midlayer3_{69586488-edb0-4c04-baba-ed091f9f04aa}_minwidth=0.381 midlayer3_{69586488-edb0-4c04-baba-ed091f9f04aa}_maxwidth=0.381 midlayer3_{69586488-edb0-4c04-baba-ed091f9f04aa}_prefwidth=0.381 midlayer4_{69586488-edb0-4c04-baba-ed091f9f04aa}_minwidth=0.381 midlayer4_{69586488-edb0-4c04-baba-ed091f9f04aa}_maxwidth=0.381 midlayer4_{69586488-edb0-4c04-baba-ed091f9f04aa}_prefwidth=0.381 bottomlayer_{69586488-edb0-4c04-baba-ed091f9f04aa}_minwidth=0.381 bottomlayer_{69586488-edb0-4c04-baba-ed091f9f04aa}_maxwidth=0.381 bottomlayer_{69586488-edb0-4c04-baba-ed091f9f04aa}_prefwidth=0.381 toplayer_minwidth=0.155 toplayer_maxwidth=0.381 toplayer_prefwidth=0.155 midlayer1_minwidth=0.155 midlayer1_maxwidth=0.381 midlayer1_prefwidth=0.155 midlayer2_minwidth=0.155 midlayer2_maxwidth=0.381 midlayer2_prefwidth=0.155 midlayer3_minwidth=0.155 midlayer3_maxwidth=0.381 midlayer3_prefwidth=0.155 midlayer4_minwidth=0.155 midlayer4_maxwidth=0.381 midlayer4_prefwidth=0.155 bottomlayer_minwidth=0.155 bottomlayer_maxwidth=0.381 bottomlayer_prefwidth=0.155 substack2={8ACABB3A-8BC0-4983-8633-DD7E9105FD50} toplayer_{8acabb3a-8bc0-4983-8633-dd7e9105fd50}_minwidth=0.381 toplayer_{8acabb3a-8bc0-4983-8633-dd7e9105fd50}_maxwidth=0.381 toplayer_{8acabb3a-8bc0-4983-8633-dd7e9105fd50}_prefwidth=0.381 midlayer1_{8acabb3a-8bc0-4983-8633-dd7e9105fd50}_minwidth=0.381 midlayer1_{8acabb3a-8bc0-4983-8633-dd7e9105fd50}_maxwidth=0.381 midlayer1_{8acabb3a-8bc0-4983-8633-dd7e9105fd50}_prefwidth=0.381 midlayer2_{8acabb3a-8bc0-4983-8633-dd7e9105fd50}_minwidth=0.381 midlayer2_{8acabb3a-8bc0-4983-8633-dd7e9105fd50}_maxwidth=0.381 midlayer2_{8acabb3a-8bc0-4983-8633-dd7e9105fd50}_prefwidth=0.381 midlayer3_{8acabb3a-8bc0-4983-8633-dd7e9105fd50}_minwidth=0.381 midlayer3_{8acabb3a-8bc0-4983-8633-dd7e9105fd50}_maxwidth=0.381 midlayer3_{8acabb3a-8bc0-4983-8633-dd7e9105fd50}_prefwidth=0.381 midlayer4_{8acabb3a-8bc0-4983-8633-dd7e9105fd50}_minwidth=0.381 midlayer4_{8acabb3a-8bc0-4983-8633-dd7e9105fd50}_maxwidth=0.381 midlayer4_{8acabb3a-8bc0-4983-8633-dd7e9105fd50}_prefwidth=0.381 bottomlayer_{8acabb3a-8bc0-4983-8633-dd7e9105fd50}_minwidth=0.381 bottomlayer_{8acabb3a-8bc0-4983-8633-dd7e9105fd50}_maxwidth=0.381 bottomlayer_{8acabb3a-8bc0-4983-8633-dd7e9105fd50}_prefwidth=0.381 substack3={A01F6CDF-020C-4B6A-8E64-FC215A2E0484} toplayer_{a01f6cdf-020c-4b6a-8e64-fc215a2e0484}_minwidth=0.381 toplayer_{a01f6cdf-020c-4b6a-8e64-fc215a2e0484}_maxwidth=0.381 toplayer_{a01f6cdf-020c-4b6a-8e64-fc215a2e0484}_prefwidth=0.381 midlayer1_{a01f6cdf-020c-4b6a-8e64-fc215a2e0484}_minwidth=0.381 midlayer1_{a01f6cdf-020c-4b6a-8e64-fc215a2e0484}_maxwidth=0.381 midlayer1_{a01f6cdf-020c-4b6a-8e64-fc215a2e0484}_prefwidth=0.381 midlayer2_{a01f6cdf-020c-4b6a-8e64-fc215a2e0484}_minwidth=0.381 midlayer2_{a01f6cdf-020c-4b6a-8e64-fc215a2e0484}_maxwidth=0.381 midlayer2_{a01f6cdf-020c-4b6a-8e64-fc215a2e0484}_prefwidth=0.381 midlayer3_{a01f6cdf-020c-4b6a-8e64-fc215a2e0484}_minwidth=0.381 midlayer3_{a01f6cdf-020c-4b6a-8e64-fc215a2e0484}_maxwidth=0.381 midlayer3_{a01f6cdf-020c-4b6a-8e64-fc215a2e0484}_prefwidth=0.381 midlayer4_{a01f6cdf-020c-4b6a-8e64-fc215a2e0484}_minwidth=0.381 midlayer4_{a01f6cdf-020c-4b6a-8e64-fc215a2e0484}_maxwidth=0.381 midlayer4_{a01f6cdf-020c-4b6a-8e64-fc215a2e0484}_prefwidth=0.381 bottomlayer_{a01f6cdf-020c-4b6a-8e64-fc215a2e0484}_minwidth=0.381 bottomlayer_{a01f6cdf-020c-4b6a-8e64-fc215a2e0484}_maxwidth=0.381 bottomlayer_{a01f6cdf-020c-4b6a-8e64-fc215a2e0484}_prefwidth=0.381 substack4={EEF93FF5-C906-4099-87FD-7A69FF981241} toplayer_{eef93ff5-c906-4099-87fd-7a69ff981241}_minwidth=0.381 toplayer_{eef93ff5-c906-4099-87fd-7a69ff981241}_maxwidth=0.381 toplayer_{eef93ff5-c906-4099-87fd-7a69ff981241}_prefwidth=0.381 midlayer1_{eef93ff5-c906-4099-87fd-7a69ff981241}_minwidth=0.381 midlayer1_{eef93ff5-c906-4099-87fd-7a69ff981241}_maxwidth=0.381 midlayer1_{eef93ff5-c906-4099-87fd-7a69ff981241}_prefwidth=0.381 midlayer2_{eef93ff5-c906-4099-87fd-7a69ff981241}_minwidth=0.381 midlayer2_{eef93ff5-c906-4099-87fd-7a69ff981241}_maxwidth=0.381 midlayer2_{eef93ff5-c906-4099-87fd-7a69ff981241}_prefwidth=0.381 midlayer3_{eef93ff5-c906-4099-87fd-7a69ff981241}_minwidth=0.381 midlayer3_{eef93ff5-c906-4099-87fd-7a69ff981241}_maxwidth=0.381 midlayer3_{eef93ff5-c906-4099-87fd-7a69ff981241}_prefwidth=0.381 midlayer4_{eef93ff5-c906-4099-87fd-7a69ff981241}_minwidth=0.381 midlayer4_{eef93ff5-c906-4099-87fd-7a69ff981241}_maxwidth=0.381 midlayer4_{eef93ff5-c906-4099-87fd-7a69ff981241}_prefwidth=0.381 bottomlayer_{eef93ff5-c906-4099-87fd-7a69ff981241}_minwidth=0.381 bottomlayer_{eef93ff5-c906-4099-87fd-7a69ff981241}_maxwidth=0.381 bottomlayer_{eef93ff5-c906-4099-87fd-7a69ff981241}_prefwidth=0.381 substack5={6741F228-4861-413B-9862-25BBBCD38B2A} toplayer_{6741f228-4861-413b-9862-25bbbcd38b2a}_minwidth=0.381 toplayer_{6741f228-4861-413b-9862-25bbbcd38b2a}_maxwidth=0.381 toplayer_{6741f228-4861-413b-9862-25bbbcd38b2a}_prefwidth=0.381 midlayer1_{6741f228-4861-413b-9862-25bbbcd38b2a}_minwidth=0.381 midlayer1_{6741f228-4861-413b-9862-25bbbcd38b2a}_maxwidth=0.381 midlayer1_{6741f228-4861-413b-9862-25bbbcd38b2a}_prefwidth=0.381 midlayer2_{6741f228-4861-413b-9862-25bbbcd38b2a}_minwidth=0.381 midlayer2_{6741f228-4861-413b-9862-25bbbcd38b2a}_maxwidth=0.381 midlayer2_{6741f228-4861-413b-9862-25bbbcd38b2a}_prefwidth=0.381 midlayer3_{6741f228-4861-413b-9862-25bbbcd38b2a}_minwidth=0.381 midlayer3_{6741f228-4861-413b-9862-25bbbcd38b2a}_maxwidth=0.381 midlayer3_{6741f228-4861-413b-9862-25bbbcd38b2a}_prefwidth=0.381 midlayer4_{6741f228-4861-413b-9862-25bbbcd38b2a}_minwidth=0.381 midlayer4_{6741f228-4861-413b-9862-25bbbcd38b2a}_maxwidth=0.381 midlayer4_{6741f228-4861-413b-9862-25bbbcd38b2a}_prefwidth=0.381 bottomlayer_{6741f228-4861-413b-9862-25bbbcd38b2a}_minwidth=0.381 bottomlayer_{6741f228-4861-413b-9862-25bbbcd38b2a}_maxwidth=0.381 bottomlayer_{6741f228-4861-413b-9862-25bbbcd38b2a}_prefwidth=0.381 maxuncoupledlength=12.7
HoleSize [All] p1: absolutevalues=TRUE maxlimit=10 minlimit=0.025 maxpercent=80.000 minpercent=20.000
HoleToHoleClearance HoleToHoleClearance_1 [(ObjectKind = 'pad') And (Name = 'CN22-PTH4') vs (ObjectKind = 'pad') And (Name = 'CN22-PTH3')] p1: gap=0 allowstackedmicrovias=TRUE
HoleToHoleClearance [(ObjectKind = 'pad') And (Name ='CN22-PTH6') vs (ObjectKind = 'pad') And (Name ='CN22-PTH5')] p2: gap=0 allowstackedmicrovias=TRUE
MatchedLengths "Schematic Matched Net Lengths_46" [InNet('USB_DEV_HS_P')] p1: tolerance=0.2 checknetsindiffpair=TRUE checkdiffpairvsdiffpair=FALSE checkxsignals=FALSE checkothers=FALSE
MatchedLengths "Schematic Matched Net Lengths_45" [InNet('USB_DEV_HS_N')] p2: tolerance=0.2 checknetsindiffpair=TRUE checkdiffpairvsdiffpair=FALSE checkxsignals=FALSE checkothers=FALSE
MatchedLengths "Schematic Matched Net Lengths_44" [InNet('USB_DEV_HS_CN_P')] p3: tolerance=0.2 checknetsindiffpair=TRUE checkdiffpairvsdiffpair=FALSE checkxsignals=FALSE checkothers=FALSE
MatchedLengths "Schematic Matched Net Lengths_43" [InNet('USB_DEV_HS_CN_N')] p4: tolerance=0.2 checknetsindiffpair=TRUE checkdiffpairvsdiffpair=FALSE checkxsignals=FALSE checkothers=FALSE
MaxMinImpedance "Schematic Impedance Constraint_7" [InNet('USB_DEV_HS_P')] p1: minimum=85.00 maximum=95.00
MaxMinImpedance "Schematic Impedance Constraint_6" [InNet('USB_DEV_HS_N')] p2: minimum=85.00 maximum=95.00
MaxMinImpedance "Schematic Impedance Constraint_5" [InNet('USB_DEV_HS_CN_P')] p3: minimum=85.00 maximum=95.00
MaxMinImpedance "Schematic Impedance Constraint_4" [InNet('USB_DEV_HS_CN_N')] p4: minimum=85.00 maximum=95.00
MinimumSolderMaskSliver [All] p1: minsoldermaskwidth=0.013
PlaneConnect [All] p1: planeconnectstyle=Relief reliefexpansion=0.508 reliefentries=4 reliefconductorwidth=0.254 reliefairgap=0.178
PolygonConnect PolygonConnect_via [IsVia] p1: connectstyle=Direct reliefconductorwidth=0.254 reliefentries=4 polygonreliefangle="90 Angle" airgapwidth=0.254
PolygonConnect [All] p2: connectstyle=Relief reliefconductorwidth=0.508 reliefentries=4 polygonreliefangle="90 Angle" airgapwidth=0.178
RoomDefinition Room_U11 [InComponent('U11')] p1: confinementstyle=ConfineIn formatcopy=TRUE lockcomponents=FALSE outline 61.211,95.199 71.041,95.199 71.041,107.094 61.211,107.094
RoomDefinition Room_U35 [InComponent('U35')] p2: confinementstyle=ConfineIn formatcopy=TRUE lockcomponents=FALSE outline 85.471,47.523 90.703,47.523 90.703,42.951 85.471,42.951
RoomDefinition Room_U40 [InComponent('U40')] p3: confinementstyle=ConfineIn formatcopy=TRUE lockcomponents=FALSE outline 74.058,35.862 85.166,35.793 85.166,24.765 74.058,24.765
RoutingVias [All] p1: holewidth=0.203 width=0.381 viastyle="Through Hole" minholewidth=0.152 minwidth=0.305 maxholewidth=0.305 maxwidth=0.508
SilkToSilkClearance LOGO [(ObjectKind = 'Text') And (Component = 'HW1')] p1: silktosilkclearance=0
SilkToSilkClearance [All] p2: silktosilkclearance=0.025
SilkToSolderMaskClearance [IsPad] p1: minsilkscreentomaskgap=0.008 clearancetoexposedcopper=TRUE
SolderMaskExpansion [All] p1: expansion=0.102 istentingtop=FALSE
Width Width_U11 [WithinRoom('Room_U11')] p1: maxlimit=0.508 minlimit=0.102 preferedwidth=0.102 substack1={69586488-EDB0-4C04-BABA-ED091F9F04AA} substack2={8ACABB3A-8BC0-4983-8633-DD7E9105FD50} substack3={A01F6CDF-020C-4B6A-8E64-FC215A2E0484} substack4={EEF93FF5-C906-4099-87FD-7A69FF981241} substack5={6741F228-4861-413B-9862-25BBBCD38B2A}
Width Width_U10 [WithinRoom('BGA_U10')] p2: maxlimit=0.254 minlimit=0.102 preferedwidth=0.102 substack1={69586488-EDB0-4C04-BABA-ED091F9F04AA} substack2={8ACABB3A-8BC0-4983-8633-DD7E9105FD50} substack3={A01F6CDF-020C-4B6A-8E64-FC215A2E0484} substack4={EEF93FF5-C906-4099-87FD-7A69FF981241} substack5={6741F228-4861-413B-9862-25BBBCD38B2A}
Width [All] p3: maxlimit=1.27 minlimit=0.102 preferedwidth=0.254 substack1={69586488-EDB0-4C04-BABA-ED091F9F04AA} toplayer_prefwidth=0.127 midlayer1_minwidth=0.127 midlayer1_maxwidth=0.512 midlayer2_minwidth=0.127 midlayer2_maxwidth=0.512 midlayer3_prefwidth=0.102 midlayer4_minwidth=0.127 midlayer4_maxwidth=0.512 bottomlayer_prefwidth=0.127 substack2={8ACABB3A-8BC0-4983-8633-DD7E9105FD50} substack3={A01F6CDF-020C-4B6A-8E64-FC215A2E0484} substack4={EEF93FF5-C906-4099-87FD-7A69FF981241} substack5={6741F228-4861-413B-9862-25BBBCD38B2A} minimp=50.000000 maximp=50.000000 favimp=50.000000
22 further rules are at their usual default settings.

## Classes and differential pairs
differential pair class 90ohm: C1_RX1 C1_RX2 C1_TX1 C1_TX2 USB_D USB_DEV_HS USB_DEV_HS_CN
component class U_HW_Mechanical_Parts: H1 H2 H3 H4 H5 H6 HW2 HW3 HW4 HW5 HW6
component class "U_Analog Interfaces": C28 C30 C35 C36 C50 C158 C159 C171 C179 C180 C181 CN3 CN7 CN8 CN9 HW18 HW19 JP5 Q4 R19 R111 R117 R124 R152 R153 R154 R157 R158 R164 R174 R179 R301 R302 R303 R304 R305 R306 R307 R308 R310 R311 R316 R318 RV1 RV2 SB16 SB22 SB75 SB102 TP1 TP2 U2 U4 U5 U7 U8 U9 U14 U53
component class U_Audio: C84 C85 C86 C87 C88 C90 C91 C92 C93 C94 C96 C97 C99 C100 C101 C103 C104 C105 C106 C107 CN23 CN26 JP16 JP17 R237 R255 R256 R257 R258 R261 U35 U41
component class "U_Debug connector": CN14 CN15 CN17 R183 R184 R185 R186 R188 R193 R195 R197 R200 R203 R205 R207 R209 R210 R211 R212 R214 U18 U20 U24
component class U_ExtensionConnector: CN5 CN6 R309 SB81 SB82 SB87 SB88
component class U_FDCAN: C40 C44 C52 C53 CN10 CN12 JP2 JP4 R163 R165 R180 R181 U10 U13 U15 U16
component class "U_FMC Memory": C46 C47 C48 R156 R162 R171 U11
component class U_LCD&SDcard: C64 C65 C69 C70 C129 C132 C186 CN20 CN24 CN28 L6 L7 Q1 R216 R218 R219 R220 R222 R226 R231 R233 R287 SB45 SB46 U26 U28 U46 U52
component class U_MB1397_TOP: HW14 JP10
component class U_MotorControl: C1 C2 C3 C4 C5 C6 C7 C8 C9 C10 C11 C12 C14 C15 C16 C17 C18 C19 C20 C21 C22 C23 C24 C25 C26 C27 C29 C31 C32 C34 C37 C38 C39 C42 CN2 CN4 CN32 R2 R3 R4 R5 R6 R7 R8 R9 R10 R11 R12 R18 R20 R21 R22 R23 R24 R25 R31 R32 R33 R51 R52 R55 R56 R57 R58 R59 R61 R64 R65 R66 R67 R72 R76 R77 R86 R91 R92 R95 R99 R100 R103 R104 R105 R106 R110 R113 R114 R115 R119 R120 R122 R125 R126 R128 R151 R155 SB2 SB14 SB19 SB32 SW1 SW2 SW3 SW4 SW5 SW6
component class "U_Multi-Function Expander": C75 C76 C77 C78 C80 C82 C83 C98 C108 C110 C111 C112 C119 C120 CN18 D7 HW21 JP13 L3 R223 R224 R225 R227 R228 R229 R230 R232 R234 R235 R236 R238 R239 R240 R241 R242 R243 R245 R252 R253 R260 R262 R265 R266 R267 R268 R270 R271 SB43 T2 T3 T4 T5 T6 T7 T8 TP6 U32 U38 U39
component class U_Peripherals: B1 B2 C13 C41 C43 C45 C49 C157 CN1 D1 L2 LD1 LD2 LD3 LD4 LD5 LPB1 R1 R13 R14 R15 R16 R17 R172 R175 R176 R177 R294 R297 R298 R299 R300 SB1 SB33 SB34 T1 TP3 U1 U3 U49 U50
component class U_Power_Board: C73 C74 C79 C95 C102 C109 C123 C124 C125 C146 C147 C149 C150 C151 C156 CN25 F1 JP12 L4 L5 LD6 R198 R247 R251 R272 R286 R289 R292 R293 RV3 SB42 SB47 SB48 TP4 TP5 TP7 TP8 TP9 U29 U33 U37 U43 U47 U48
component class "U_QSPI Memory": C51 C184 R159 R160 R161 R166 R167 R168 R169 R170 R173 R178 R319 R320 R321 R322 SB35 SB36 SB119 SB120 U12 U54
component class U_RS232&RS485: C54 C55 C56 C57 C58 C60 C61 C62 CN11 JP9 R190 R191 R192 R201 R202 R213 SB37 SB38 SB39 SB40 U17 U22 U23
component class U_SmartCard: C121 C126 C127 C152 C153 C154 C155 CN31 D10 HW6 R273 R274 R275 R276 R290 R291 TP10 TP11 U42 U44
component class U_STLink_V3E_SWD: C63 C66 C67 C68 C71 C72 C81 C89 C113 C114 C115 C116 C117 C118 C122 C128 C130 C131 C133 C134 C135 C136 C137 C138 C139 C140 C141 C142 C143 C144 C145 C148 CN16 CN21 CN27 CN29 CN30 D3 D4 D5 D6 LD7 LD8 R187 R189 R194 R196 R199 R204 R206 R208 R215 R217 R221 R269 R277 R278 R279 R280 R281 R282 R283 R284 R285 R288 R295 R296 SB41 U19 U21 U25 U27 U31 U34 U40 U45 X1
component class U_STM32_microcontroller_IOs: HW24 JP1 R26 R27 R28 R29 R30 R34 R35 R36 R37 R38 R39 R40 R41 R42 R43 R44 R45 R46 R47 R48 R49 R50 R53 R54 R60 R62 R63 R68 R69 R70 R71 R73 R74 R75 R78 R79 R80 R81 R82 R83 R84 R85 R87 R88 R89 R90 R93 R94 R96 R97 R98 R101 R102 R107 R108 R109 R112 R116 R118 R121 R123 R127 R129 R130 R131 R132 R133 R134 R135 R136 R137 R138 R139 R140 R141 R142 R143 R144 R145 R146 R147 R148 R149 R150 SB3 SB4 SB5 SB6 SB7 SB8 SB9 SB10 SB11 SB12 SB13 SB15 SB17 SB18 SB20 SB21 SB23 SB24 SB25 SB26 SB27 SB28 SB29 SB49 SB50 SB51 SB52 SB53 SB54 SB55 SB56 SB57 SB58 SB59 SB60 SB61 SB62 SB63 SB64 SB65 SB66 SB67 SB68 SB69 SB70 SB71 SB72 SB73 SB74 SB76 SB77 SB78 SB79 SB80 SB83 SB89 SB91 SB92 SB93 SB94 SB95 SB96 SB97 SB98 SB99 SB100 SB101 SB103 SB104 SB105 SB106 SB107 SB108 SB109 SB110 SB111 SB112 SB113 SB114 SB115 SB116 SB117 SB118 SB123 U6
component class U_STM32_microcontroller_power: B3 C33 C59 C160 C161 C162 C163 C164 C165 C166 C167 C168 C169 C170 C172 C173 C174 C175 C176 C177 C178 C182 C183 CN13 D2 D11 HW15 HW16 HW17 HW25 JP6 JP7 JP8 JP11 JP18 L1 L8 L9 R182 R312 R313 R314 R315 R317 SB30 SB31 SB84 SB85 SB86 SB90 SW7 U51 X2 X3
component class U_USB-TYPEC_CON: CN19 CN22 SB121 SB122 U30 U36 U55
component class U_USB_PD: C185 D8 D9 HW22 HW23 JP14 JP15 Q2 Q3 R244 R246 R248 R249 R250 R254 R259 R263 R264 R323 SB44 T9 T10
net class A[0..18]: A0 A1 A2 A3 A4 A5 A6 A7 A8 A9 A10 A11 A12 A13 A14 A15 A16 A17 A18 A19 A20
net class D[0..15]: D0 D1 D2 D3 D4 D5 D6 D7 D8 D9 D10 D11 D12 D13 D14 D15
net class PA[0..15]: PA0 PA1 PA2 PA3 PA4 PA5 PA6 PA7 PA8 PA9 PA10 PA11 PA12 PA13 PA14 PA15
net class PB[0..15]: PB0 PB1 PB2 PB3 PB4 PB5 PB6 PB7 PB8 PB9 PB10 PB11 PB12 PB13 PB14 PB15
net class PC[0..15]: PC0 PC1 PC2 PC3 PC4 PC5 PC6 PC7 PC8 PC9 PC10 PC11 PC12 PC13 PC14 PC15
net class PD[0..15]: PD0 PD1 PD2 PD3 PD4 PD5 PD6 PD7 PD8 PD9 PD10 PD11 PD12 PD13 PD14 PD15
net class PE[0..15]: PE0 PE1 PE2 PE3 PE4 PE5 PE6 PE7 PE8 PE9 PE10 PE11 PE12 PE13 PE14 PE15
net class PF[0..15]: PF0 PF1 PF2 PF3 PF4 PF5 PF6 PF7 PF8 PF9 PF10 PF11 PF12 PF13 PF14 PF15
net class PG[0..15]: PG0 PG1 PG2 PG3 PG4 PG5 PG6 PG7 PG8 PG9 PG10 PG11 PG12 PG13 PG14 PG15
differential pair C1_TX2: +C1_TX2+ -C1_TX2-
differential pair C1_RX2: +C1_RX2- -C1_RX2+
differential pair C1_TX1: +C1_TX1+ -C1_TX1-
differential pair C1_RX1: +C1_RX1+ -C1_RX1-
differential pair USB_D: +USB_DM -USB_DP
differential pair USB_DEV_HS_CN: +USB_DEV_HS_CN_P -USB_DEV_HS_CN_N
differential pair USB_DEV_HS: +USB_DEV_HS_P -USB_DEV_HS_N
differential pair USB_DEV_HS_CN: +USB_DEV_HS_CN_P -USB_DEV_HS_CN_N
differential pair USB_DEV_HS: +USB_DEV_HS_P -USB_DEV_HS_N

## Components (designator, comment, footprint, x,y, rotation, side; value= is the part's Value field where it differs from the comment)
B1 "Joystick MT-008A_M" SWI_XIEJIA_MT-008A_6P 64.889,6.37 r45 top
B2 "SW_BLUE_KSC721GLFS" SWI_C&K_KSC721GLFS_BLUE 50.414,6.318 r0 top
B3 "SW-PUSH-CMS" SWI_WEALTHMETAL_TD-0341_4P_BLACK 80.14,5.875 r90 top
C1 "Capacitor" C0402 90.17,158.115 r90 top
C2 "Capacitor" C0402 68.981,157.988 r270 top
C3 "Capacitor" C0402 53.527,158.287 r0 top
C4 "Capacitor" C0402 77.938,157.887 r90 top
C5 "Capacitor" C0402 62.27,157.845 r270 top
C6 "Capacitor" C0402 71.587,157.845 r270 top
C7 "Capacitor" C0402 64.801,157.837 r270 top
C8 "Capacitor" C0402 74.129,157.837 r270 top
C9 "Capacitor" C0402 48.486,157.785 r90 top
C10 "Capacitor" C0402 50.8,157.737 r270 top
C11 "Capacitor" C0402 49.654,157.731 r90 top
C12 "Capacitor" C0402 53.527,157.087 r0 top
C13 "Capacitor" C0603 25.651,154.897 r180 top
C14 "Capacitor" C0603 25.113,152.448 r180 top
C15 "Capacitor" C0603 25.121,148.511 r180 top
C16 "Capacitor" C0402 10.668,148.709 r180 top
C17 "Capacitor" C0603 92.913,143.711 r90 top
C18 "Capacitor" C0603 25.146,141.732 r180 top
C19 "Capacitor" C0603 92.905,140.645 r270 top
C20 "Capacitor" C0603 92.956,136.466 r270 top
C21 "Capacitor" C0603 25.113,135.509 r0 top
C22 "Capacitor" C0402 10.668,134.941 r180 top
C23 "Capacitor" C0402 10.735,129.237 r0 top
C24 "Capacitor" C0402 10.735,126.794 r0 top
C25 "Capacitor" C0603 25.121,125.12 r0 top
C26 "Capacitor" C0402 10.735,124.028 r0 top
C27 "Capacitor" C0603 93.086,123.221 r90 top
C28 "Capacitor" C0603 111.858,123.175 r0 top
C29 "Capacitor" C0402 10.735,122.301 r0 top
C30 "Capacitor" C0603 114.757,121.808 r180 top
C31 "Capacitor" C0402 10.785,119.717 r0 top
C32 "Capacitor" C0603 25.146,118.684 r0 top
C33 "Capacitor" C0402 112.003,113.335 r270 top
C34 "Capacitor" C0402 10.668,112.268 r0 top
C35 "Capacitor" C0603 79.781,111.433 r270 top
C36 "Capacitor" C0603 89.662,110.894 r0 top
C37 "Capacitor" C0402 10.044,109.773 r270 top
C38 "Capacitor" C0402 11.294,109.773 r270 top
C39 "Capacitor" C0402 10.668,107.06 r180 top
C40 "Capacitor" C0402 29.25,106.364 r90 top
C41 "Cap_POL_TANA" CPOL_TAJ-C_2312_H2P6 49.454,103.342 r270 top
C42 "Capacitor" C0402 10.668,105.816 r180 top
C43 "Capacitor" C0603 42.44,104.835 r270 top
C44 "Capacitor" C0402 37.45,104.306 r270 top
C45 "Capacitor" C0603 40.442,104.151 r0 top
C46 "Capacitor" C0603 59.757,102.256 r0 top
C47 "Capacitor" C0402 72.533,101.573 r0 top
C48 "Capacitor" C0402 59.876,101.088 r180 top
C49 "Capacitor" C0402 50.15,98.45 r180 top
C50 "Capacitor" C0402 106.934,97.948 r90 top
C51 "Capacitor" C0402 89.762,97.966 r180 top
C52 "Capacitor" C0402 29.303,97.48 r90 top
C53 "Capacitor" C0402 37.45,95.124 r270 top
C54 "Capacitor" C0402 15.24,88.645 r270 top
C55 "Capacitor" C0402 16.256,88.62 r270 top
C56 "Capacitor" C0402 26.924,87.713 r90 top
C57 "Capacitor" C0402 28.42,87.655 r90 top
C58 "Capacitor" C0402 26.924,85.598 r90 top
C59 "Capacitor" C0402 68.227,85.148 r90 top
C60 "Capacitor" C0603 15.748,77.689 r90 top
C61 "Capacitor" C0603 24.039,66.487 r270 top
C62 "Capacitor" C0603 25.563,66.482 r90 top
C63 "Capacitor" C0402 51.757,62.537 r180 top
C64 "Capacitor" C0603 84.021,61.464 r180 top
C65 "Capacitor" C0603 91.031,61.337 r180 top
C66 "Capacitor" C0603 51.751,61.156 r0 top
C67 "Capacitor" C0603 54.839,58.216 r270 top
C68 "Capacitor" C0603 56.543,58.216 r270 top
C69 "Capacitor" C0603 84.071,58.619 r180 top
C70 "Capacitor" C0603 91.031,58.594 r180 top
C71 "Capacitor" C0402 49.817,58.066 r270 top
C72 "Capacitor" C0402 60.706,57.297 r90 top
C73 "Capacitor" C0603 90.412,54.857 r90 top
C74 "Capacitor" C0402 83.954,55.527 r0 top
C75 "Capacitor" C0603 76.313,54.395 r270 top
C76 "Capacitor" C0603 67.861,54.353 r270 top
C77 "Capacitor" C0402 69.145,54.395 r270 top
C78 "Capacitor" C0402 69.945,54.353 r270 top
C79 "Capacitor" C0603 83.954,53.911 r0 top
C80 "Capacitor" C0402 78.129,53.238 r180 top
C81 "Capacitor" C0603 111.027,50.572 r180 top
C82 "Capacitor" C0402 79.908,50.221 r90 top
C83 "Capacitor" C0402 80.772,50.213 r270 top
C84 "Capacitor" C0603 85.529,49.626 r270 top
C85 "Capacitor" C0603 86.763,49.626 r90 top
C86 "Capacitor" C0603 89.339,49.626 r270 top
C87 "Capacitor" C0603 90.552,49.626 r90 top
C88 "Capacitor" C0603 88.04,49.601 r270 top
C89 "Capacitor" C0603 111.027,49.302 r0 top
C90 "Capacitor" C0603 92.487,48.701 r180 top
C91 "Capacitor" C0603 92.487,47.373 r180 top
C92 "Capacitor" C0603 83.597,47.119 r0 top
C93 "Capacitor" C0402 92.422,46.284 r0 top
C94 "Capacitor" C0402 83.597,46.077 r180 top
C95 "Capacitor" C0402 25.064,46.038 r180 top
C96 "Capacitor" C0402 92.422,45.466 r0 top
C97 "Capacitor" C0603 83.547,44.856 r0 top
C98 "Capacitor" C0402 62.858,44.455 r0 top
C99 "Capacitor" C0603 92.433,44.117 r0 top
C100 "Capacitor" C0402 92.303,43.078 r0 top
C101 "Capacitor" C0603 83.597,42.822 r0 top
C102 "Capacitor" C0805 32.332,41.704 r0 top
C103 "Capacitor" C0603 92.71,40.665 r90 top
C104 "Capacitor" C0603 94.107,40.665 r90 top
C105 "Capacitor" C0603 91.448,40.656 r90 top
C106 "Capacitor" C0402 89.047,40.565 r270 top
C107 "Capacitor" C0402 86.761,40.538 r270 top
C108 "Capacitor" C0603 46.955,40.607 r180 top
C109 "Cap_POL_TANA" CPOL_TAJ-C_2312_H2P6 32.459,38.862 r180 top
C110 "Capacitor" C0603 38.219,39.425 r0 top
C111 "Capacitor" C0603 46.405,38.744 r90 top
C112 "Capacitor" C0603 50.189,38.735 r270 top
C113 "Capacitor" C0603 83.782,37.486 r270 top
C114 "Capacitor" C0603 81.011,37.472 r270 top
C115 "Capacitor" C1206_H1P15 74.433,37.472 r0 top
C116 "Capacitor" C0402 77.347,37.419 r270 top
C117 "Capacitor" C0402 78.497,37.419 r270 top
C118 "Capacitor" C0402 82.307,37.419 r270 top
C119 "Capacitor" C0603 52.539,37.472 r0 top
C120 "Capacitor" C0603 38.219,36.723 r0 top
C121 "Cap_POL_TANA" CPOL_TAJ-C_2312_H2P6 54.636,34.313 r180 top
C122 "Capacitor" C1206_H1P15 86.402,33.675 r270 top
C123 "Capacitor" C1210 21.488,33.106 r90 top
C124 "Capacitor" C1210 18.059,33.096 r90 top
C125 "Capacitor" C0402 23.641,32.93 r90 top
C126 "Capacitor" C0603 62.013,31.288 r90 top
C127 "Capacitor" C0603 56.277,31.088 r0 top
C128 "Capacitor" C0402 86.371,30.926 r180 top
C129 "Capacitor" C0805 94.945,29.235 r270 top
C130 "Capacitor" C0402 86.332,29.918 r180 top
C131 "Capacitor" C0402 72.401,29.799 r0 top
C132 "Capacitor" C0402 96.342,29.286 r90 top
C133 "Capacitor" C0402 72.393,28.912 r0 top
C134 "Capacitor" C0402 72.401,25.798 r0 top
C135 "Capacitor" C0603 72.233,23.703 r90 top
C136 "Capacitor" C0402 73.417,23.518 r90 top
C137 "Capacitor" C0402 80.54,23.449 r90 top
C138 "Capacitor" C0402 75.703,23.449 r90 top
C139 "Capacitor" C0402 76.758,23.449 r90 top
C140 "Capacitor" C0402 77.647,23.449 r90 top
C141 "Capacitor" C0402 79.59,23.449 r90 top
C142 "Capacitor" C0402 83.577,23.449 r90 top
C143 "Capacitor" C0402 84.541,23.449 r90 top
C144 "Capacitor" C0402 85.471,23.449 r90 top
C145 "Capacitor" C0402 82.607,23.449 r90 top
C146 "Capacitor" C0402 41.323,20.742 r180 top
C147 "Capacitor" C0402 19.304,20.263 r90 top
C148 "Capacitor" C0402 75.73,20.31 r0 top
C149 "Capacitor" C0603 38.215,17.694 r270 top
C150 "Capacitor" C0603 34.663,17.656 r90 top
C151 "Capacitor" C0603 29.55,17.54 r270 top
C152 "Cap_POL_TANA" CPOL_TAJ-C_2312_H2P6 50.395,16.25 r180 top
C153 "Capacitor" C0603 54.988,16.33 r90 top
C154 "Capacitor" C0603 56.36,16.304 r90 top
C155 "Capacitor" C0603 57.63,16.304 r270 top
C156 "Capacitor" C0603 42.442,15.204 r90 top
C157 "Capacitor" C0402 50.8,10.668 r270 top
C158 "Capacitor" C0603 113.403,150.607 r0 bottom
C159 "Capacitor" C0603 110.931,147.441 r270 bottom
C160 "Capacitor" C0402 60.903,136.586 r180 bottom
C161 "Capacitor" C0402 67.603,136.566 r180 bottom
C162 "Capacitor" C0402 74.323,134.716 r90 bottom
C163 "Capacitor" C0603 59.817,129.692 r90 bottom
C164 "Capacitor" C0402 58.603,129.666 r270 bottom
C165 "Capacitor" C0402 72.103,128.303 r90 bottom
C166 "Capacitor" C0805 71.704,126.026 r90 bottom
C167 "Capacitor" C0603 76.417,125.899 r270 bottom
C168 "Capacitor" C0402 73.66,126.159 r90 bottom
C169 "Capacitor" C0402 74.524,126.144 r90 bottom
C170 "Capacitor" C0402 75.397,126.111 r90 bottom
C171 "Capacitor" C0603 75.717,123.749 r180 bottom
C172 "Capacitor" C0402 66.403,123.571 r180 bottom
C173 "Capacitor" C0402 59.083,123.166 r270 bottom
C174 "Capacitor" C0402 69.825,122.022 r180 bottom
C175 "Capacitor" C0402 65.1,121.336 r270 bottom
C176 "Capacitor" C0402 72.339,121.638 r0 bottom
C177 "Capacitor" C0402 69.803,120.866 r180 bottom
C178 "Capacitor" C0402 71.003,118.999 r270 bottom
C179 "Capacitor" C0603 110.846,118.82 r90 bottom
C180 "Capacitor" C0603 109.601,118.82 r90 bottom
C181 "Capacitor" C0402 114.907,119.047 r270 bottom
C182 "Capacitor" C0402 64.348,119.151 r180 bottom
C183 "Capacitor" C0402 62.459,119.126 r0 bottom
C184 "Capacitor" C0402 89.645,103.76 r90 bottom
C185 "Capacitor" C0603 12.913,49.083 r0 bottom
C186 "Capacitor" C0402 96.365,15.415 r0 bottom
CN1 "Socket 4x2" CON_SAMTEC_SSM-104-L-DH 22.135,165.159 r90 top
CN2 "Header 17x2 IDC34 MotorControl" CON_SAMTEC_TST-117-01-T-D 71.12,164.465 r180 top locked
CN3 "SMB-ZJWE-3" CON_JACK-RIGHT-ANGLE_YJ-ELECTRONIC_SMB-ZJWE-3 113.884,156.464 r0 top
CN4 "Header 17x2 IDC34 MotorControl" CON_SAMTEC_TST-117-01-T-D 4.445,128.905 r270 top locked
CN5 "Header 30x2" CON_SAMTEC_FTR-130-53-L-D-LC 33.835,131.396 r270 top locked
CN6 "Header 30x2" CON_SAMTEC_FTR-130-53-L-D-LC 102.415,131.396 r270 top
CN7 "SMB-ZJWE-3" CON_JACK-RIGHT-ANGLE_YJ-ELECTRONIC_SMB-ZJWE-3 113.884,141.285 r0 top
CN8 "SMB-ZJWE-3" CON_JACK-RIGHT-ANGLE_YJ-ELECTRONIC_SMB-ZJWE-3 113.831,129.474 r0 top
CN9 "Jumper_Header 2x1" CON_SAMTEC_TSW-102-07-G-S 88.147,115.279 r0 top
CN10 "Header 2x1" CON_988-JIUBABA_PHFS25-11-02-G0B115-T-1 19.186,104.06 r90 top
CN11 "DB9_Header_male_3-1634580-2" CON_DB9-MALE_TYCO_3-1634580-2 1.644,84.833 r270 top locked
CN12 "Header 2x1" CON_988-JIUBABA_PHFS25-11-02-G0B115-T-1 19.186,95.037 r90 top
CN13 "BATTERY HOLDER" BAT_HARWIN_S8411-45R_SMD_2P 59.992,82.804 r90 top
CN14 "Header 10x2" CON_CVILUX_CH87-20-2-V-1-00 112.395,74.93 r270 top locked
CN15 "Tag-10-C" CON_TAG-C_TC2050-IDC-NL 96.924,83.828 r180 top
CN16 "Header 7x2" CON_STDC14_Receiver_MEDIUM_WITH_MIPI10_3D 86.226,73.577 r90 top
CN17 "Header 10x2" CON_SAMTEC_FTSH-110-01-L-DV-A 96.393,73.458 r270 top
CN18 "Header 4x1" CON_SAMTEC_TSW-104-07-G-S 67.069,70.993 r270 top
CN19 "Header 10x2" CON_SAMTEC_FTSH-110-01-L-DV-A 8.001,61.595 r0 top
CN20 "Socket 4x2_LCD_IO_MODULE_MB895C" CON_SOCKET-LCD_LYCN_216208S141 100.33,57.15 r270 top locked
CN21 "USB_uB_105017.0001" CON_USBMICROB_MOLEX_105017-0001_H2P90 118.088,52.721 r90 top
CN22 "USB Type-C" CON_USB-TYPEC_LITKCONN-TECHNOLOGY_CNG008S130R -0.164,48.159 r270 top locked
CN23 "Jack_PJ3028B-3_3P" CON_PHONE-JACK-3P5_HY_PJ3028B 118.11,41.783 r180 top
CN24 "Socket 4x2_LCD_PWR_MODULE_MB895C" CON_SOCKET-LCD_LYCN_216208S141 100.33,31.75 r270 top locked
CN25 "Power_Jack_DC10B" CON_DC-POWER-SOCKET_CLIFF_FC68149_DC10B -3.5,19.977 r180 top
CN26 "Jack_PJ3028B-3_3P" CON_PHONE-JACK-3P5_HY_PJ3028B 118.091,20.574 r180 top
CN27 "Header 4x1" CON_SAMTEC_TSW-104-07-G-S 84.455,14.504 r270 top
CN28 "microSD-PJS008-2003" CON_MICROSD_YAMAICHI_PJS008-2003-1 94.748,0.025 r270 top locked
CN29 "Header 2x1" CON_988-JIUBABA_PHFS25-11-02-G0B115-T-1 107.341,13.066 r0 top
CN30 "Header 2x1" CON_988-JIUBABA_PHFS25-11-02-G0B115-T-1 114.485,13.066 r0 top
CN31 "Please to check it carefuly. Pin 8 and 9 not clearly define on datasheet. Need to validate with schematics symbol" CON_CARD-SOCKET_GUANG-LIAN-WEI_2480-208-503-100-RC 56.991,20.665 r270 bottom locked
CN32 "Jumper_Header 2x1" CON_SAMTEC_TSW-102-07-G-S 88.062,118.613 r0 top
D1 "SCHOTTKY" DIO_SMA_1A_2K 45.339,103.708 r270 top
D2 "BAT60JFILM" DIO_SOD323 84.401,82.219 r90 top
D3 "BAT60JFILM" DIO_SOD323 45.8,61.824 r270 top
D4 "BAT60JFILM" DIO_SOD323 44.041,61.815 r270 top
D5 "BAT60JFILM" DIO_SOD323 42.219,61.808 r270 top
D6 "BAT60JFILM" DIO_SOD323 47.594,61.74 r270 top
D7 "BAT60JFILM" DIO_SOD323 72.207,55.067 r90 top
D8 "STPS2L40UF" DIO_SMB-FLAT_1A_2K 16.323,52.08 r270 top
D9 "STPS2L40UF" DIO_SMB-FLAT_1A_2K 21.053,52.023 r270 top
D10 "EMIF03-SIM02M8" ESD_UQFN8-EPAD_1P7X1P5_P040 64.094,31.483 r0 top
D11 "BAT60JFILM" DIO_SOD323 78.283,10.363 r180 top
Designator42 "Comment" STICKER_25X9 28.931,163.88 r180 bottom
F1 "0ZCG0260FF2C" PTC_BEL-FUSE_1812_0ZCG0260FF2C 15.397,15.554 r0 top
H1 "POSITION HOLE C7D3R5" PTH_350_700 7.62,167.005 r0 top locked
H2 "POSITION HOLE C7D3R5" PTH_350_700 110.49,167.005 r0 top locked
H3 "POSITION HOLE C3R5D3R5" NPTH_350 21.617,59.817 r0 top locked
H4 "POSITION HOLE C3R5D3R5" NPTH_350 21.617,23.807 r0 top locked
H5 "POSITION HOLE C7D3R5" PTH_350_700 7.62,5.715 r0 top locked
H6 "POSITION HOLE C7D3R5" PTH_350_700 110.49,5.715 r0 top locked
HW2 "Logo" LOGO_ST 39.703,165.227 r0 top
